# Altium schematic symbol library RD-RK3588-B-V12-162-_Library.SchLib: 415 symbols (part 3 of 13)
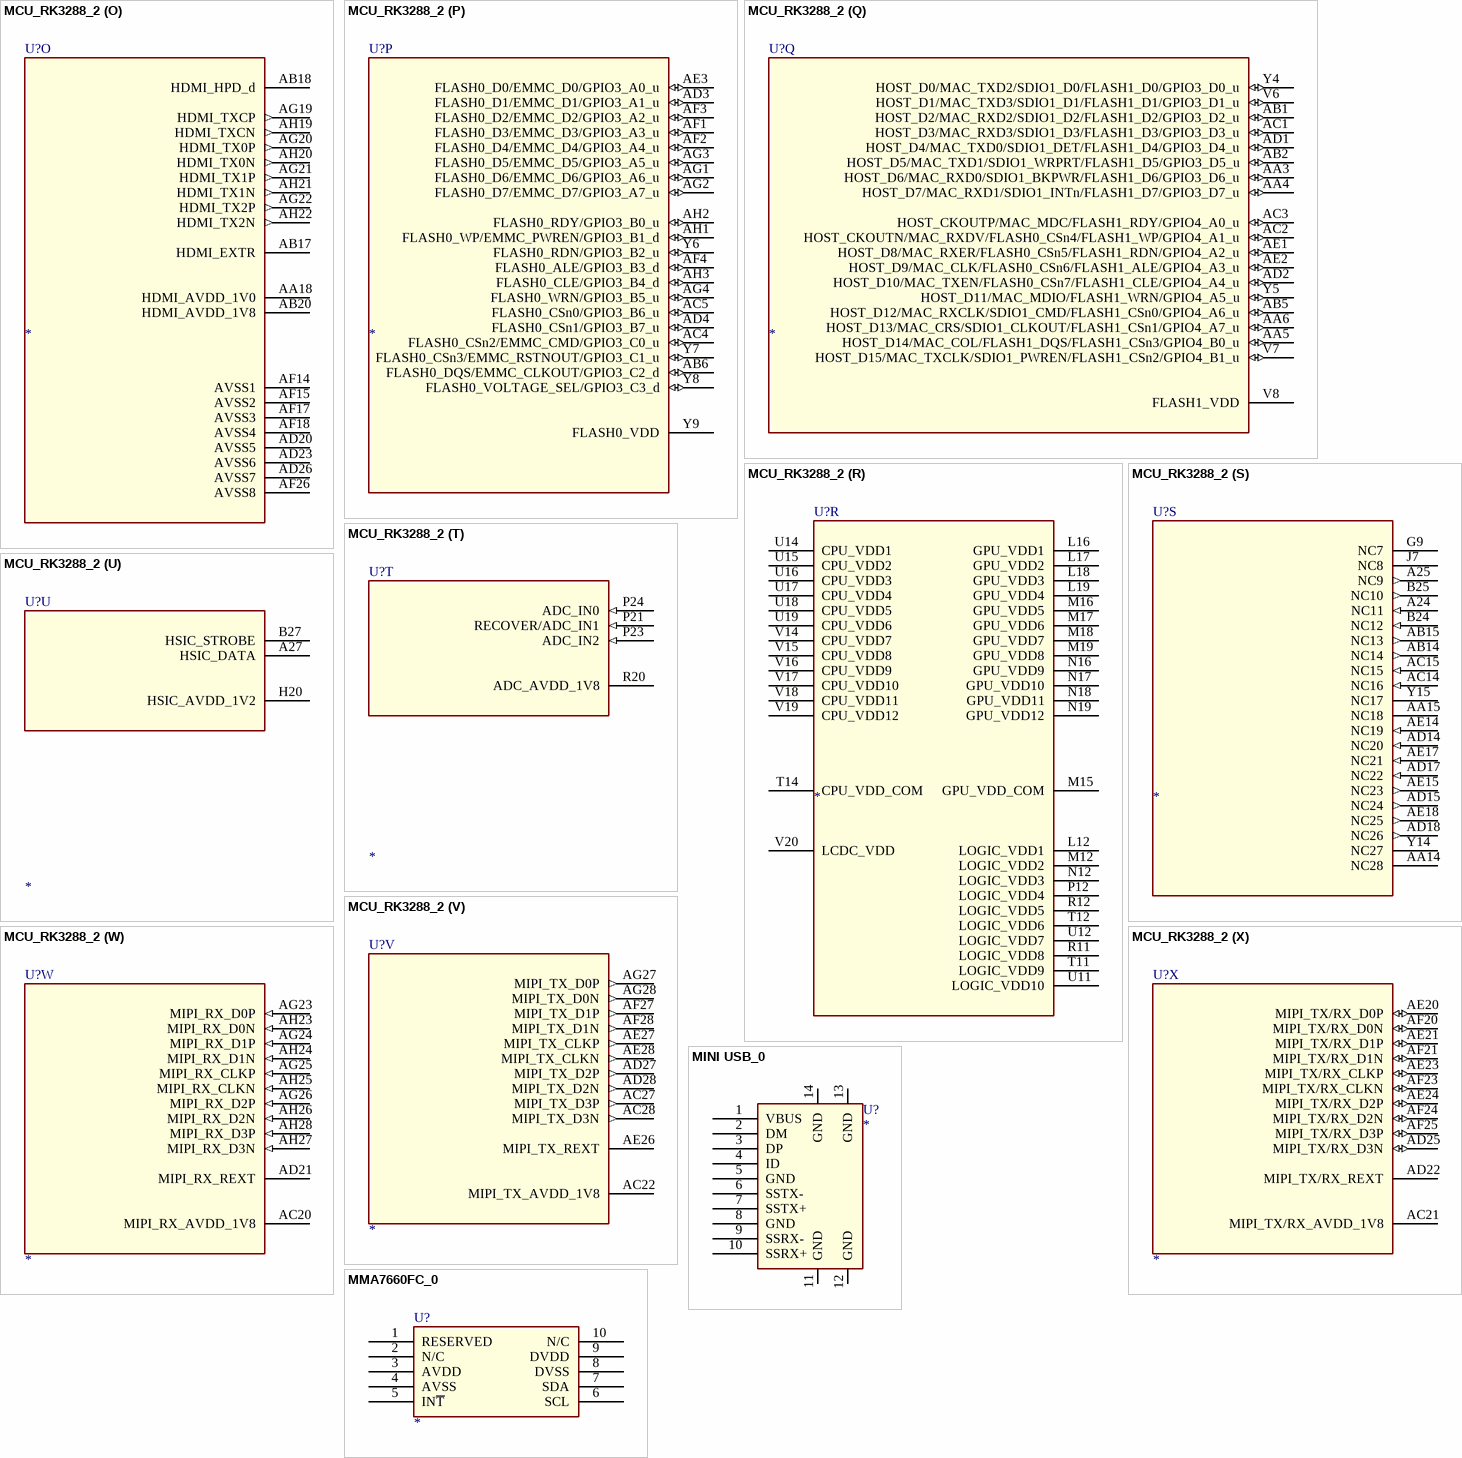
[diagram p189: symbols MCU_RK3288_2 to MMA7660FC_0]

## MCU_RK3288_2
designator U?
footprint BGA453-19X19
part A pins: AA20 LVDS_AVDD_1V0 (power), AA22 LCDC0_DEN/GPIO1_D2_d (io), AA23 LCDC0_HSYNC/GPIO1_D0_d (io), AA24 LCDC0_DCLK/GPIO1_D3_d (io), AA25 TRACE_CLK/LCDC0_D16/LVDS_D7P (io), AA26 TRACE_CTL/LCDC0_D17/LVDS_D7N (io), AA27 TRACE_D8/LCDC0_D8/LVDS_D4P (io), AA28 TRACE_D9/LCDC0_D9/LVDS_D4N (io), AB21 LVDS_AVDD_1V8 (power), AB23 LVDS_AVDD_3V3 (power), AB24 LCDC0_VSYNC/GPIO1_D1_d (io), AB27 LCDC0_D18/LVDS_D8P (io), AB28 LCDC0_D19/LVDS_D8N (io), AC25 LCDC0_D20/LVDS_D9P (io), AC26 LCDC0_D21/LVDS_D9N (io), T27 TRACE_D0/LCDC0_D0/LVDS_D0P (io), T28 TRACE_D1/LCDC0_D1/LVDS_D0N (io), U25 TRACE_D12/LCDC0_D12/LVDS_D5P (io), U26 TRACE_D13/LCDC0_D13/LVDS_D5N (io), U27 TRACE_D2/LCDC0_D2/LVDS_D1P (io), U28 TRACE_D3/LCDC0_D3/LVDS_D1N (io), V24 LVDS_EXTR, V25 TRACE_D14/LCDC0_D14/LVDS_D6P (io), V26 TRACE_D15/LCDC0_D15/LVDS_D6N (io), V27 TRACE_D10/LCDC0_D10/LVDS_CLK0P (io), V28 TRACE_D11/LCDC0_D11/LVDS_CLK0N (io), W27 TRACE_D4/LCDC0_D4/LVDS_D2P (io), W28 TRACE_D5/LCDC0_D5/LVDS_D2N (io), Y25 LCDC0_D22/LVDS_CLK1P (io), Y26 LCDC0_D23/LVDS_CLK1N (io), Y27 TRACE_D6/LCDC0_D6/LVDS_D3P (io), Y28 TRACE_D7/LCDC0_D7/LVDS_D3N (io)
part B pins: AB9 JTAG_TCK/SDMMC0_D3/GPIO6_C3_u (io), AC8 SDMMC0_CMD/GPIO6_C5_u (io), AC9 SDMMC0_VDD (power), AD8 JTAG_TDI/SDMMC0_D2/GPIO6_C2_u (io), AG6 JTAG_TDO/SDMMC0_CLKOUT/GPIO6_C4_d (io), AG7 JTAG_TMS/SDMMC0_D0/GPIO6_C0_u (io), AH5 SDMMC0_DET/GPIO6_C6_u (io), AH6 JTAG_TRSTN/SDMMC0_D1/GPIO6_C1_u (io)
part C pins: P22 I2C3_SCL/GPIO2_C0_u (io), R21 CIF_D11/GPIO2_B7_d (io), R22 HOST_WKREQ/TS_FAIL/CIF_CLKOUT/GPIO2_B3_d (io), R23 I2C3_SDA/GPIO2_C1_u (io), R24 CIF_D10/GPIO2_B6_d (io), R25 HOST_D6/TS_SYNC/CIF_VSYNC/GPIO2_B0_d (io), R26 CIF_D1/GPIO2_B5_d (io), R27 CIF_D0/GPIO2_B4_d (io), R28 HOST_D7/TS_VALID/CIF_HREF/GPIO2_B1_d (io), U20 DVPIO_VDD (power), U21 HOST_CKINN/TS_D5/CIF_D7/GPIO2_A5_d (io), U22 HOST_CKINP/TS_D4/CIF_D6/GPIO2_A4_d (io), U23 HOST_D4/TS_D6/CIF_D8/GPIO2_A6_d (io), V21 HOST_D3/TS_D3/CIF_D5/GPIO2_A3_d (io), V22 HOST_WKACK/GPS_CLK/TS_CLKOUT/CIF_CLKIN/GPIO2_B2_d (io), V23 HOST_D5/TS_D7/CIF_D9/GPIO2_A7_d (io), Y21 HOST_D1/TS_D1/CIF_D3/GPIO2_A1_d (io), Y22 HOST_D2/TS_D2/CIF_D4/GPIO2_A2_d (io), Y23 HOST_D0/TS_D0/CIF_D2/GPIO2_A0_d (io)
part D pins: J26 DDRIO_RETEN/PMUGPIO0_A2_u (io), J27 DDRIO_PWROFF/PMUGPIO0_A1_d (io), J28 GLOBAL_PWROFF/PMUGPIO0_A0_d (io), K27 EFUSE_PWREN/PMUGPIO0_A3_u (io), K28 PMUGPIO0_A4_u, L21 PMUGPIO0_A5_u, L22 PMUGPIO0_A6_u (io), L23 PMUGPIO0_A7_u (io), L24 PMUGPIO0_B0_u, L25 PMUGPIO0_B1_u, L26 OTP_OUT/PMUGPIO0_B2_d (io), L27 PMUGPIO0_B3_d (io), L28 CLK27M_IN/PMUGPIO0_B5_d (io), M20 PMU_VDD_1V0 (power), M21 I2C0_SCL/PMUGPIO0_C0_u (io), M22 PMUGPIO0_B6_d (io), M23 TEST_CLKO/CLK_27M_T1/PMUGPIO0_C1_d (io), M24 PMUGPIO0_C2_u (io), M25 I2C0_SDA/PMUGPIO0_B7_u (io), M26 TEST, M27 NPOR (in), M28 PMUGPIO0_B4_d (io), N27 OSC_XI (in), N28 OSC_XO (out), P19 EFUSE_VQPS (power), P20 PUMIO_VDD (power), P25 CLKIN_32K (in), P26 OSC_XVSS (power), P27 PLL_AVSS (power), P28 PLL_AVDD_1V0 (power)
part E pins: A22 HOST2_DM (io), A23 HOST1_DM (io), A26 OTG_DM (io), B21 USB_AVSS4 (power), B22 HOST2_DP (io), B23 HOST1_DP (io), B26 OTG_DP (io), C21 HOST2_EXTR, C23 HOST1_EXTR, C24 USB_AVSS2 (power), C25 OTG_ID, C26 USB_AVSS3 (power), D21 OTG_EXTR, D23 OTG_VBUS, E21 USB_AVDD_1V8 (power), F20 USB_AVDD_3V3 (power), G18 USB_AVDD_1V0 (power), H18 USB_AVSS1 (power)
part F pins: D28 GPIO7_A2_d (io), E26 GPIO7_A4_u (io), E27 GPS_MAG/HSADC_D0_T1/UART3_RX/GPIO7_A7_u, E28 eDP_HOTPLUG/GPIO7_B3_d (io), F25 GPIO7_A3_d (io), F26 GPIO7_A6_u (io), F27 UART3_RTSn/GPIO7_B2_u (io), F28 ISP_PRELIGHTTRIG/SPI1_RXD/GPIO7_B6_d (io), G23 PWM1/GPIO7_A1_d (io), G24 GPIO7_A5_d (io), G27 ISP_SHUTTERTRIG/SPI1_TXD/GPIO7_B7_d (io), G28 ISP_FLASHTRIGIN/EDPHDMI_CEC_T1/GPIO7_C0_u (io), H22 PWM0/GPIO7_A0_d (io), H23 GPS_RFCLK/GPS_CLK_T1/UART3_CTSn/GPIO7_B1_u (io), H24 ISP_FLASHTRIGOUT/SPI1_CSN0/GPIO7_B5_u (io), H25 I2C4_SDA/GPIO7_C1_u (io), H26 I2C5_SDA/EDPHDMI_I2C_SDA/GPIO7_C3_u (io), H27 GPIO7_C5_d (io), H28 UART2_TX/IR_TX/PWM3/EDPHDMI_CEC/GPIO7_C7_u (io), J21 GPS_SIG/HSADC_D1_T1/UART3_TX/GPIO7_B0_d (io), J22 ISP_SHUTTEREN/SPI1_CLK/GPIO7_B4_d (io), J23 I2C4_SCL/GPIO7_C2_u (io), J24 I2C5_SCL/EDPHDMI_I2C_SCL/GPIO7_C4_u (io), J25 UART2_RX/IR_RX/PWM2/GPIO7_C6_u, L20 APIO1_VDD (power)
part G pins: A28 I2C1_SDA/SC_RST/GPIO8_A4_u (io), B28 SPI2_CSn1/SC_IO/GPIO8_A3_u (io), C27 PS2_DATA/GPIO8_A1_u (io), C28 SPI2_TXD/SC_CLK_T1/GPIO8_B1_d (io), D24 PS2_CLK/GPIO8_A0_u (io), D26 SPI2_CLK/SC_IO_T1/GPIO8_A6_d (io), D27 SPI2_CSn0/SC_DET_T1/GPIO8_A7_u (io), E22 BS_JTAG_TRSTn (out), E23 BS_JTAG_TCK (out), E25 I2C1_SCL/SC_CLK/GPIO8_A5_u (io), F21 BS_JTAG_TDI (in), F22 BS_JTAG_TDO (out), F24 SPI2_RXD/SC_RST_T1/GPIO8_B0_d (io), G20 BS_JTAG_TMS (out), G21 SC_DET/GPIO8_A2_u (io), J20 APIO2_VDD (power)
part H pins: AA11 APIO3_VDD (power), AB11 UART0_RTSn/GPIO4_C3_u (io), AB12 UART0_CTSn/GPIO4_C2_u (io), AC11 SDIO0_PWR/GPIO4_D4_d (io), AD9 GPIO4_D7_u (io), AE8 SDIO0_INTn/GPIO4_D6_u (io), AE9 SDIO0_WP/GPIO4_D3_d (io), AF8 SDIO0_BKPWR/GPIO4_D5_d (io), AF9 SDIO0_DET/GPIO4_D2_u (io), AG8 SDIO0_CLKOUT/GPIO4_D1_d (io), AG9 SDIO0_D2/GPIO4_C6_u (io), AG10 UART0_TXD/GPIO4_C1_d (io), AH7 SDIO0_D3/GPIO4_C7_u (io), AH8 SDIO0_CMD/GPIO4_D0_u (io), AH9 SDIO0_D0/GPIO4_C4_u (io), AH10 SDIO0_D1/GPIO4_C5_u (io), AH11 UART0_RXD/GPIO4_C0_u (io)
part I pins: AC12 I2S_CLK/GPIO6_B0_d (io), AD11 I2S_SCLK/GPIO6_A0_d (io), AD12 I2C2_SCL/GPIO6_B2_u (io), AE11 I2S_SDI/GPIO6_A3_d (io), AE12 SPDIF_TX/GPIO6_B3_d (io), AF11 I2S_LRCK_TX/GPIO6_A2_d (io), AF12 I2C2_SDA/GPIO6_B1_u (io), AG11 I2S_LRCK_RX/GPIO6_A1_d (io), AG12 I2S_SDO0/GPIO6_A4_d (io), AG13 I2S_SDO2/GPIO6_A6_d (io), AH12 I2S_SDO3/GPIO6_A7_d (io), AH13 I2S_SDO1/GPIO6_A5_d (io), Y12 APIO4_VDD (power)
part J pins: AA7 UART1_TX/TS0_D1/GPIO5_B1_d (io), AA9 TS0_VALID/GPIO5_C1_d (io), AB8 TS0_ERR/GPIO5_C3_d (io), AC7 SPI0_CSn0/UART4_RTSn/TS0_D5/GPIO5_B5_u (io), AD6 UART1_RTSn/TS0_D3/GPIO5_B3_u (io), AD7 SPI0_CLK/UART4_CTSn/TS0_D4/GPIO5_B4_u (io), AE5 SPI0_TXD/UART4_TX/TS0_D6/GPIO5_B6_d, AE6 TS0_CLK/GPIO5_C2_d (io), AF5 UART1_RX/TS0_D0/GPIO5_B0_u, AF6 SPI0_RXD/UART4_RX/TS0_D7/GPIO5_B7_u, AG5 SPI0_CSn1/TS0_SYNC/GPIO5_C0_u (io), AH4 UART1_CTSn/TS0_D2/GPIO5_B2_u (io), Y11 APIO5_VDD (power)
part K pins: A1 DDR0_DQ25 (io), A2 DDR0_DQ24 (io), A3 DDR0_DQ10 (io), A4 DDR0_DQS3n (out), A5 DDR0_DQ9 (io), A6 DDR0_DQ13 (io), A7 DDR0_DQS1n (out), A8 DDR0_CASn (out), A9 DDR0_BA1 (out), A10 DDR0_A2 (out), A11 DDR0_CLKn (out), A12 DDR0_A7 (out), A13 DDR0_A10 (out), A14 DDR0_A9 (out), A15 DDR0_DM2 (out), A16 DDR0_DQ17 (io), A17 DDR0_DQS2n (out), A18 DDR0_DQ23 (io), A19 DDR0_DQ4 (io), A20 DDR0_DQS0 (out), B3 DDR0_DM3 (out), B4 DDR0_DQS3 (out), B5 DDR0_DQ8 (io), B6 DDR0_DQ14 (io), B7 DDR0_DQS1 (out), B8 DDR0_CSn0 (out), B9 DDR0_WEn (out), B10 DDR0_A0 (out), B11 DDR0_CLK (out), B12 DDR0_A5 (out), B13 DDR0_A8 (out), B14 DDR0_A14 (out), B15 DDR0_DQ16 (io), B16 DDR0_DQ19 (io), B17 DDR0_DQS2 (out), B18 DDR0_DQ21 (io), B19 DDR0_DQ0 (io), B20 DDR0_DQS0n (out), C4 DDR0_DQ30 (io), C5 DDR0_DQ28 (io), C6 DDR0_DQ11 (io), C8 DDR0_CKE1 (out), C9 DDR0_CKE0 (out), C11 DDR0_A1 (out), C12 DDR0_A6 (out), C14 DDR0_A13 (out), C15 DDR0_A15 (out), C17 DDR0_DQ22 (io), C18 DDR0_DQ1 (io), C20 DDR0_DQ6 (io), D5 DDR0_DQ26 (io), D8 DDR0_BA0 (out), D11 DDR0_RASn (out), D14 DDR0_A11 (out), D17 DDR0_DQ20 (io), D20 DDR0_DQ7 (io), E6 DDR0_DQ27 (io), E7 DDR0_DQ31 (io), E8 DDR0_DQ12 (io), E9 DDR0_RESET (out), E11 DDR0_BA2 (out), E12 DDR0_A3 (out), E14 DDR0_ODT0 (out), E15 DDR0_ODT1 (out), E17 DDR0_DM0 (out), E18 DDR0_DQ5 (io), F7 DDR0_DQ29 (io), F8 DDR0_DQ15 (io), F9 DDR0_DM1 (out), F11 DDR0_CSn1 (out), F12 DDR0_A4 (out), F14 DDR0_A12 (out), F15 DDR0_DQ18 (io), F17 DDR0_DQ2 (io), F18 DDR0_DQ3 (io), G8 DDR0_RETLE, G11 NC3, G12 DDR0_ATO, G14 NC1, G15 NC2, G17 DDR0_PZQ, H9 DDR0_VDD1 (power), H11 DDR0_VREFAO (power), H12 DDR0_VREF (power), H14 DDR0_VDDAO (power), H15 DDR0_DTO1, H17 DDR0_DTO0, J11 DDR0_VDD2 (power), J12 DDR0_VDD3 (power), J14 DDR0_VDD4 (power), J15 DDR0_VDD5 (power)
part L pins: AA1 DDR1_DQS0n (out), AA2 DDR1_DQS0 (out), B1 DDR1_DQ24 (io), B2 DDR1_DQ25 (io), C1 DDR1_DQ10 (io), C2 DDR1_DQ30 (io), D1 DDR1_DQS3n (out), D2 DDR1_DQS3 (out), D3 DDR1_DM3 (out), E1 DDR1_DQ9 (io), E2 DDR1_DQ8 (io), E3 DDR1_DQ28 (io), E4 DDR1_DQ26 (io), F1 DDR1_CKE0 (out), F2 DDR1_RESET (out), F3 DDR1_DQ11 (io), F5 DDR1_DQ29 (io), G1 DDR1_DQS1n (out), G2 DDR1_DQS1 (out), G5 DDR1_DM1 (out), G6 DDR1_DQ27 (io), H1 DDR1_CASn (out), H2 DDR1_CSn0 (out), H3 DDR1_CKE1 (out), H4 DDR1_DQ13 (io), H5 DDR1_DQ12 (io), H6 DDR1_DQ31 (io), H7 DDR1_RETLE, J1 DDR1_BA1 (out), J2 DDR1_WEn (out), J3 DDR1_CSn1 (out), J5 DDR1_DQ14 (io), J6 DDR1_DQ15 (io), J8 DDR1_VDD1 (power), K1 DDR1_A2 (out), K2 DDR1_A1 (out), L1 DDR1_CLKn (out), L2 DDR1_CLK (out), L3 DDR1_A0 (out), L4 DDR1_BA0 (out), L5 DDR1_BA2 (out), L6 DDR1_RASn (out), L7 NC6, L8 DDR1_VREFAO (power), L9 DDR1_VDD2 (power), M1 DDR1_A6 (out), M2 DDR1_A5 (out), M3 DDR1_A7 (out), M5 DDR1_A3 (out), M6 DDR1_A4 (out), M7 DDR1_ATO, M8 DDR1_VREF (power), M9 DDR1_VDD3 (power), N1 DDR1_A8 (out), N2 DDR1_A10 (out), P1 DDR1_A9 (out), P2 DDR1_A14 (out), P3 DDR1_A13 (out), P4 DDR1_A11 (out), P5 DDR1_ODT0 (out), P6 DDR1_A12 (out), P7 NC4, P8 DDR1_VDDAO (power), P9 DDR1_VDD4 (power), R1 DDR1_A15 (out), R2 DDR1_ODT1 (out), R3 DDR1_DM2 (out), R5 DDR1_DQ19 (io), R6 DDR1_DQ17 (io), R7 NC5, R8 DDR1_DTO1, R9 DDR1_VDD5 (power), T1 DDR1_DQ18 (io), T2 DDR1_DQ16 (io), U1 DDR1_DQS2n (out), U2 DDR1_DQS2 (out), U3 DDR1_DQ22 (io), U4 DDR1_DQ20 (io), U5 DDR1_DM0 (out), U6 DDR1_DQ3 (io), U7 DDR1_PZQ, U8 DDR1_DTO0, V1 DDR1_DQ21 (io), V2 DDR1_DQ23 (io), V3 DDR1_DQ1 (io), V5 DDR1_DQ6 (io), W1 DDR1_DQ4 (io), W2 DDR1_DQ0 (io), Y1 DDR1_DQ2 (io), Y2 DDR1_DQ5 (io), Y3 DDR1_DQ7 (io)
part M pins: A21 VSS9 (power), AC24 VSS11 (power), C3 VSS1 (power), D6 VSS2 (power), D9 VSS3 (power), D12 VSS4 (power), D15 VSS5 (power), D18 VSS6 (power), E20 VSS7 (power), F4 VSS12 (power), J4 VSS13 (power), J9 VSS14 (power), J17 VSS16 (power), J18 VSS28 (power), K10 VSS18 (power), K11 VSS19 (power), K12 VSS20 (power), K13 VSS21 (power), K14 VSS22 (power), K15 VSS23 (power), K16 VSS24 (power), K17 VSS25 (power), K18 VSS26 (power), K19 VSS27 (power), L10 VSS29 (power), L11 VSS30 (power), L13 VSS31 (power), L14 VSS32 (power), L15 VSS33 (power), M4 VSS34 (power), M10 VSS35 (power), M11 VSS36 (power), M13 VSS37 (power), M14 VSS38 (power), N10 VSS40 (power), N11 VSS41 (power), N13 VSS42 (power), N14 VSS43 (power), N15 VSS44 (power), P10 VSS45 (power), P11 VSS46 (power), P13 VSS47 (power), P14 VSS48 (power), P15 VSS49 (power), P16 VSS50 (power), P17 VSS51 (power), P18 VSS52 (power), R4 VSS53 (power), R10 VSS54 (power), R13 VSS55 (power), R14 VSS61 (power), R15 VSS71 (power), R16 VSS56 (power), R17 VSS57 (power), R18 VSS58 (power), R19 VSS59 (power), T10 VSS60 (power), T13 VSS62 (power), T15 VSS64 (power), T16 VSS65 (power), T17 VSS66 (power), T18 VSS67 (power), T19 VSS68 (power), U9 VSS15 (power), U10 VSS70 (power), U13 VSS72 (power), U24 VSS8 (power), V4 VSS73 (power), V9 VSS69 (power), V10 VSS74 (power), V11 VSS75 (power), V12 VSS76 (power), V13 VSS77 (power), W10 VSS17 (power), W11 VSS78 (power), W12 VSS79 (power), W13 VSS80 (power), W14 VSS81 (power), W15 VSS82 (power), W16 VSS83 (power), W17 VSS84 (power), W18 VSS85 (power), W19 VSS86 (power), Y18 VSS39 (power), Y20 VSS63 (power), Y24 VSS10 (power)
part N pins: AA12 eDP_TP_OUT, AA17 eDP_AVDD_1V8 (power), AC17 eDP_CLK24M_IN, AC18 eDP_EXTR, AG14 eDP_TX0P (out), AG15 eDP_TX1P (out), AG16 eDP_TX2P (out), AG17 eDP_TX3P (out), AG18 eDP_AXUP (out), AH14 eDP_TX0N (out), AH15 eDP_TX1N (out), AH16 eDP_TX2N (out), AH17 eDP_TX3N (out), AH18 eDP_AXUN (out), Y17 eDP_AVDD_1V0 (power)
part O pins: AA18 HDMI_AVDD_1V0 (power), AB17 HDMI_EXTR, AB18 HDMI_HPD_d, AB20 HDMI_AVDD_1V8 (power), AD20 AVSS5 (power), AD23 AVSS6 (power), AD26 AVSS7 (power), AF14 AVSS1 (power), AF15 AVSS2 (power), AF17 AVSS3 (power), AF18 AVSS4 (power), AF26 AVSS8 (power), AG19 HDMI_TXCP (out), AG20 HDMI_TX0P (out), AG21 HDMI_TX1P (out), AG22 HDMI_TX2P (out), AH19 HDMI_TXCN (out), AH20 HDMI_TX0N (out), AH21 HDMI_TX1N (out), AH22 HDMI_TX2N (out)
part P pins: AB6 FLASH0_DQS/EMMC_CLKOUT/GPIO3_C2_d (io), AC4 FLASH0_CSn2/EMMC_CMD/GPIO3_C0_u (io), AC5 FLASH0_CSn0/GPIO3_B6_u (io), AD3 FLASH0_D1/EMMC_D1/GPIO3_A1_u (io), AD4 FLASH0_CSn1/GPIO3_B7_u (io), AE3 FLASH0_D0/EMMC_D0/GPIO3_A0_u (io), AF1 FLASH0_D3/EMMC_D3/GPIO3_A3_u (io), AF2 FLASH0_D4/EMMC_D4/GPIO3_A4_u (io), AF3 FLASH0_D2/EMMC_D2/GPIO3_A2_u (io), AF4 FLASH0_ALE/GPIO3_B3_d (io), AG1 FLASH0_D6/EMMC_D6/GPIO3_A6_u (io), AG2 FLASH0_D7/EMMC_D7/GPIO3_A7_u (io), AG3 FLASH0_D5/EMMC_D5/GPIO3_A5_u (io), AG4 FLASH0_WRN/GPIO3_B5_u (io), AH1 FLASH0_WP/EMMC_PWREN/GPIO3_B1_d (io), AH2 FLASH0_RDY/GPIO3_B0_u (io), AH3 FLASH0_CLE/GPIO3_B4_d (io), Y6 FLASH0_RDN/GPIO3_B2_u (io), Y7 FLASH0_CSn3/EMMC_RSTNOUT/GPIO3_C1_u (io), Y8 FLASH0_VOLTAGE_SEL/GPIO3_C3_d (io), Y9 FLASH0_VDD (power)
part Q pins: AA3 HOST_D6/MAC_RXD0/SDIO1_BKPWR/FLASH1_D6/GPIO3_D6_u (io), AA4 HOST_D7/MAC_RXD1/SDIO1_INTn/FLASH1_D7/GPIO3_D7_u (io), AA5 HOST_D14/MAC_COL/FLASH1_DQS/FLASH1_CSn3/GPIO4_B0_u (io), AA6 HOST_D13/MAC_CRS/SDIO1_CLKOUT/FLASH1_CSn1/GPIO4_A7_u (io), AB1 HOST_D2/MAC_RXD2/SDIO1_D2/FLASH1_D2/GPIO3_D2_u (io), AB2 HOST_D5/MAC_TXD1/SDIO1_WRPRT/FLASH1_D5/GPIO3_D5_u (io), AB5 HOST_D12/MAC_RXCLK/SDIO1_CMD/FLASH1_CSn0/GPIO4_A6_u (io), AC1 HOST_D3/MAC_RXD3/SDIO1_D3/FLASH1_D3/GPIO3_D3_u (io), AC2 HOST_CKOUTN/MAC_RXDV/FLASH0_CSn4/FLASH1_WP/GPIO4_A1_u (io), AC3 HOST_CKOUTP/MAC_MDC/FLASH1_RDY/GPIO4_A0_u (io), AD1 HOST_D4/MAC_TXD0/SDIO1_DET/FLASH1_D4/GPIO3_D4_u (io), AD2 HOST_D10/MAC_TXEN/FLASH0_CSn7/FLASH1_CLE/GPIO4_A4_u (io), AE1 HOST_D8/MAC_RXER/FLASH0_CSn5/FLASH1_RDN/GPIO4_A2_u (io), AE2 HOST_D9/MAC_CLK/FLASH0_CSn6/FLASH1_ALE/GPIO4_A3_u (io), V6 HOST_D1/MAC_TXD3/SDIO1_D1/FLASH1_D1/GPIO3_D1_u (io), V7 HOST_D15/MAC_TXCLK/SDIO1_PWREN/FLASH1_CSn2/GPIO4_B1_u (io), V8 FLASH1_VDD (power), Y4 HOST_D0/MAC_TXD2/SDIO1_D0/FLASH1_D0/GPIO3_D0_u (io), Y5 HOST_D11/MAC_MDIO/FLASH1_WRN/GPIO4_A5_u (io)
part R pins: L12 LOGIC_VDD1 (power), L16 GPU_VDD1 (power), L17 GPU_VDD2 (power), L18 GPU_VDD3 (power), L19 GPU_VDD4 (power), M12 LOGIC_VDD2 (power), M15 GPU_VDD_COM, M16 GPU_VDD5 (power), M17 GPU_VDD6 (power), M18 GPU_VDD7 (power), M19 GPU_VDD8 (power), N12 LOGIC_VDD3 (power), N16 GPU_VDD9 (power), N17 GPU_VDD10 (power), N18 GPU_VDD11 (power), N19 GPU_VDD12 (power), P12 LOGIC_VDD4 (power), R11 LOGIC_VDD8 (power), R12 LOGIC_VDD5 (power), T11 LOGIC_VDD9 (power), T12 LOGIC_VDD6 (power), T14 CPU_VDD_COM, U11 LOGIC_VDD10 (power), U12 LOGIC_VDD7 (power), U14 CPU_VDD1 (power), U15 CPU_VDD2 (power), U16 CPU_VDD3 (power), U17 CPU_VDD4 (power), U18 CPU_VDD5 (power), U19 CPU_VDD6 (power), V14 CPU_VDD7 (power), V15 CPU_VDD8 (power), V16 CPU_VDD9 (power), V17 CPU_VDD10 (power), V18 CPU_VDD11 (power), V19 CPU_VDD12 (power), V20 LCDC_VDD (power)
part S pins: A24 NC11 (in), A25 NC9 (out), AA14 NC28 (power), AA15 NC18 (power), AB14 NC14 (out), AB15 NC13 (out), AC14 NC16 (in), AC15 NC15 (in), AD14 NC20 (in), AD15 NC24 (out), AD17 NC22 (in), AD18 NC26 (out), AE14 NC19 (in), AE15 NC23 (out), AE17 NC21 (in), AE18 NC25 (out), B24 NC12 (in), B25 NC10 (out), G9 NC7, J7 NC8, Y14 NC27 (power), Y15 NC17 (power)
part T pins: P21 RECOVER/ADC_IN1 (in), P23 ADC_IN2 (in), P24 ADC_IN0 (in), R20 ADC_AVDD_1V8 (power)
part U pins: A27 HSIC_DATA, B27 HSIC_STROBE, H20 HSIC_AVDD_1V2 (power)
part V pins: AC22 MIPI_TX_AVDD_1V8 (power), AC27 MIPI_TX_D3P (out), AC28 MIPI_TX_D3N (out), AD27 MIPI_TX_D2P (out), AD28 MIPI_TX_D2N (out), AE26 MIPI_TX_REXT, AE27 MIPI_TX_CLKP (out), AE28 MIPI_TX_CLKN (out), AF27 MIPI_TX_D1P (out), AF28 MIPI_TX_D1N (out), AG27 MIPI_TX_D0P (out), AG28 MIPI_TX_D0N (out)
part W pins: AC20 MIPI_RX_AVDD_1V8 (power), AD21 MIPI_RX_REXT, AG23 MIPI_RX_D0P (in), AG24 MIPI_RX_D1P (in), AG25 MIPI_RX_CLKP (in), AG26 MIPI_RX_D2P (in), AH23 MIPI_RX_D0N (in), AH24 MIPI_RX_D1N (in), AH25 MIPI_RX_CLKN (in), AH26 MIPI_RX_D2N (in), AH27 MIPI_RX_D3N (in), AH28 MIPI_RX_D3P (in)
part X pins: AC21 MIPI_TX/RX_AVDD_1V8 (power), AD22 MIPI_TX/RX_REXT, AD25 MIPI_TX/RX_D3N (io), AE20 MIPI_TX/RX_D0P (io), AE21 MIPI_TX/RX_D1P (io), AE23 MIPI_TX/RX_CLKP (io), AE24 MIPI_TX/RX_D2P (io), AF20 MIPI_TX/RX_D0N (io), AF21 MIPI_TX/RX_D1N (io), AF23 MIPI_TX/RX_CLKN (io), AF24 MIPI_TX/RX_D2N (io), AF25 MIPI_TX/RX_D3P (io)

## MINI USB_0
designator U?
pins: 1 VBUS, 2 DM, 3 DP, 4 ID, 5 GND, 6 SSTX-, 7 SSTX+, 8 GND (power), 9 SSRX-, 10 SSRX+, 11 GND, 12 GND, 13 GND, 14 GND

## MMA7660FC_0
designator U?
pins: 1 RESERVED, 2 N/C, 3 AVDD, 4 AVSS, 5 IN~{T}, 6 SCL, 7 SDA, 8 DVSS, 9 DVDD, 10 N/C

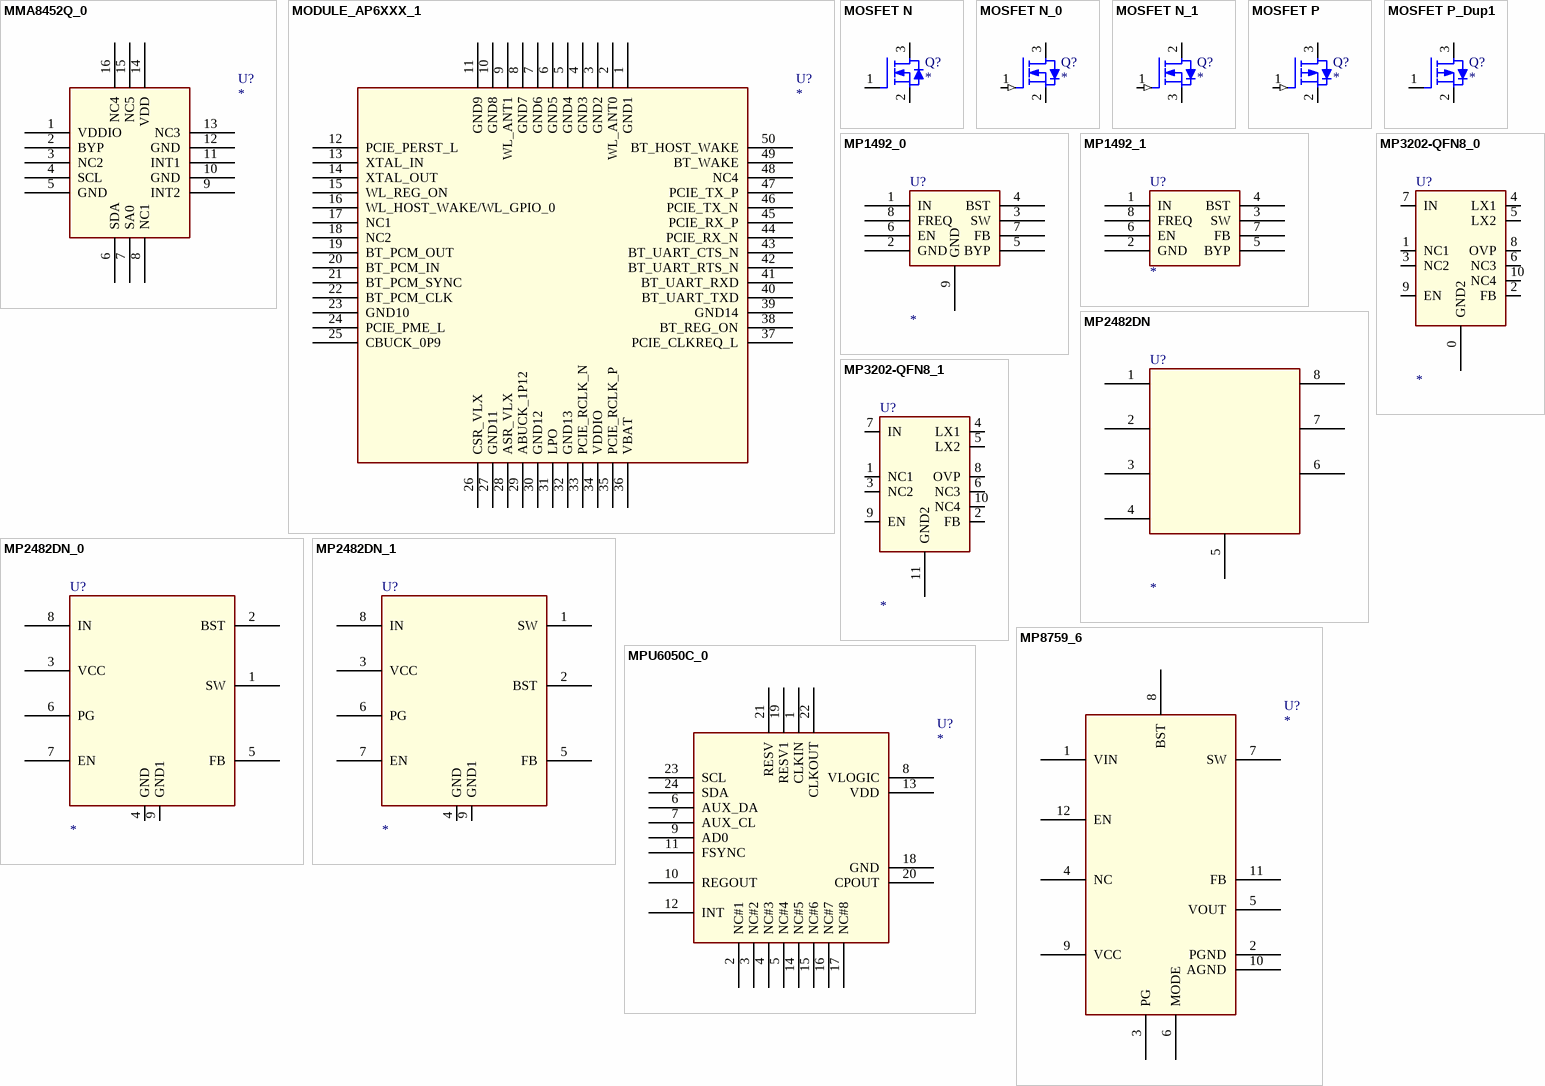
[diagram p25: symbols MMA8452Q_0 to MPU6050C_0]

## MMA8452Q_0
designator U?
footprint QFN16_COL
pins: 1 VDDIO, 2 BYP, 3 NC2, 4 SCL, 5 GND (power), 6 SDA, 7 SA0, 8 NC1, 9 INT2, 10 GND (power), 11 INT1, 12 GND (power), 13 NC3, 14 VDD, 15 NC5, 16 NC4

## MODULE_AP6XXX_1
designator U?
pins: 1 GND1, 2 WL_ANT0, 3 GND2, 4 GND3, 5 GND4, 6 GND5, 7 GND6, 8 GND7, 9 WL_ANT1, 10 GND8, 11 GND9, 12 PCIE_PERST_L, 13 XTAL_IN, 14 XTAL_OUT, 15 WL_REG_ON, 16 WL_HOST_WAKE/WL_GPIO_0, 17 NC1, 18 NC2, 19 BT_PCM_OUT, 20 BT_PCM_IN, 21 BT_PCM_SYNC, 22 BT_PCM_CLK, 23 GND10, 24 PCIE_PME_L, 25 CBUCK_0P9, 26 CSR_VLX, 27 GND11, 28 ASR_VLX, 29 ABUCK_1P12, 30 GND12, 31 LPO, 32 GND13, 33 PCIE_RCLK_N, 34 VDDIO, 35 PCIE_RCLK_P, 36 VBAT, 37 PCIE_CLKREQ_L, 38 BT_REG_ON, 39 GND14, 40 BT_UART_TXD, 41 BT_UART_RXD, 42 BT_UART_RTS_N, 43 BT_UART_CTS_N, 44 PCIE_RX_N, 45 PCIE_RX_P, 46 PCIE_TX_N, 47 PCIE_TX_P, 48 NC4, 49 BT_WAKE, 50 BT_HOST_WAKE

## MOSFET N
designator Q?
footprint SOT23
pins: 1 GATE, 2 SOURCE, 3 DRAIN

## MOSFET N_0
designator Q?
pins: 1 GATE (in), 2 SOURCE, 3 DRAIN

## MOSFET N_1
designator Q?
pins: 1 GATE (in), 2 DRAIN, 3 SOURCE

## MOSFET P
designator Q?
footprint SOT23
pins: 1 GATE (in), 2 SOURCE, 3 DRAIN

## MOSFET P_Dup1
designator Q?
footprint SOT23
pins: 1 GATE, 2 SOURCE, 3 DRAIN

## MP1492_0
designator U?
footprint SOP8A
pins: 1 IN, 2 GND, 3 SW, 4 BST, 5 BYP, 6 EN, 7 FB, 8 FREQ, 9 GND

## MP1492_1
designator U?
footprint SOP8A
pins: 1 IN, 2 GND, 3 SW, 4 BST, 5 BYP, 6 EN, 7 FB, 8 FREQ

## MP2482DN
designator U?
pins: 1, 2, 3, 4, 5, 6, 7, 8

## MP2482DN_0
designator U?
pins: 1 SW, 2 BST, 3 VCC, 4 GND, 5 FB, 6 PG, 7 EN, 8 IN, 9 GND1

## MP2482DN_1
designator U?
pins: 1 SW, 2 BST, 3 VCC, 4 GND, 5 FB, 6 PG, 7 EN, 8 IN, 9 GND1

## MP3202-QFN8_0
designator U?
footprint QFN8-2X2
pins: 0 GND2, 1 NC1, 2 FB, 3 NC2, 4 LX1, 5 LX2, 6 NC3, 7 IN, 8 OVP, 9 EN, 10 NC4

## MP3202-QFN8_1
designator U?
footprint QFN8-2X2
pins: 1 NC1, 2 FB, 3 NC2, 4 LX1, 5 LX2, 6 NC3, 7 IN, 8 OVP, 9 EN, 10 NC4, 11 GND2

## MP8759_6
designator U?
footprint QFN12_2R00X3R00X1R00
pins: 1 VIN, 2 PGND, 3 PG, 4 NC, 5 VOUT, 6 MODE, 7 SW, 8 BST, 9 VCC, 10 AGND, 11 FB, 12 EN

## MPU6050C_0
designator U?
pins: 1 CLKIN, 2 NC#1, 3 NC#2, 4 NC#3, 5 NC#4, 6 AUX_DA, 7 AUX_CL, 8 VLOGIC, 9 AD0, 10 REGOUT, 11 FSYNC, 12 INT, 13 VDD, 14 NC#5, 15 NC#6, 16 NC#7, 17 NC#8, 18 GND, 19 RESV1, 20 CPOUT, 21 RESV, 22 CLKOUT, 23 SCL, 24 SDA

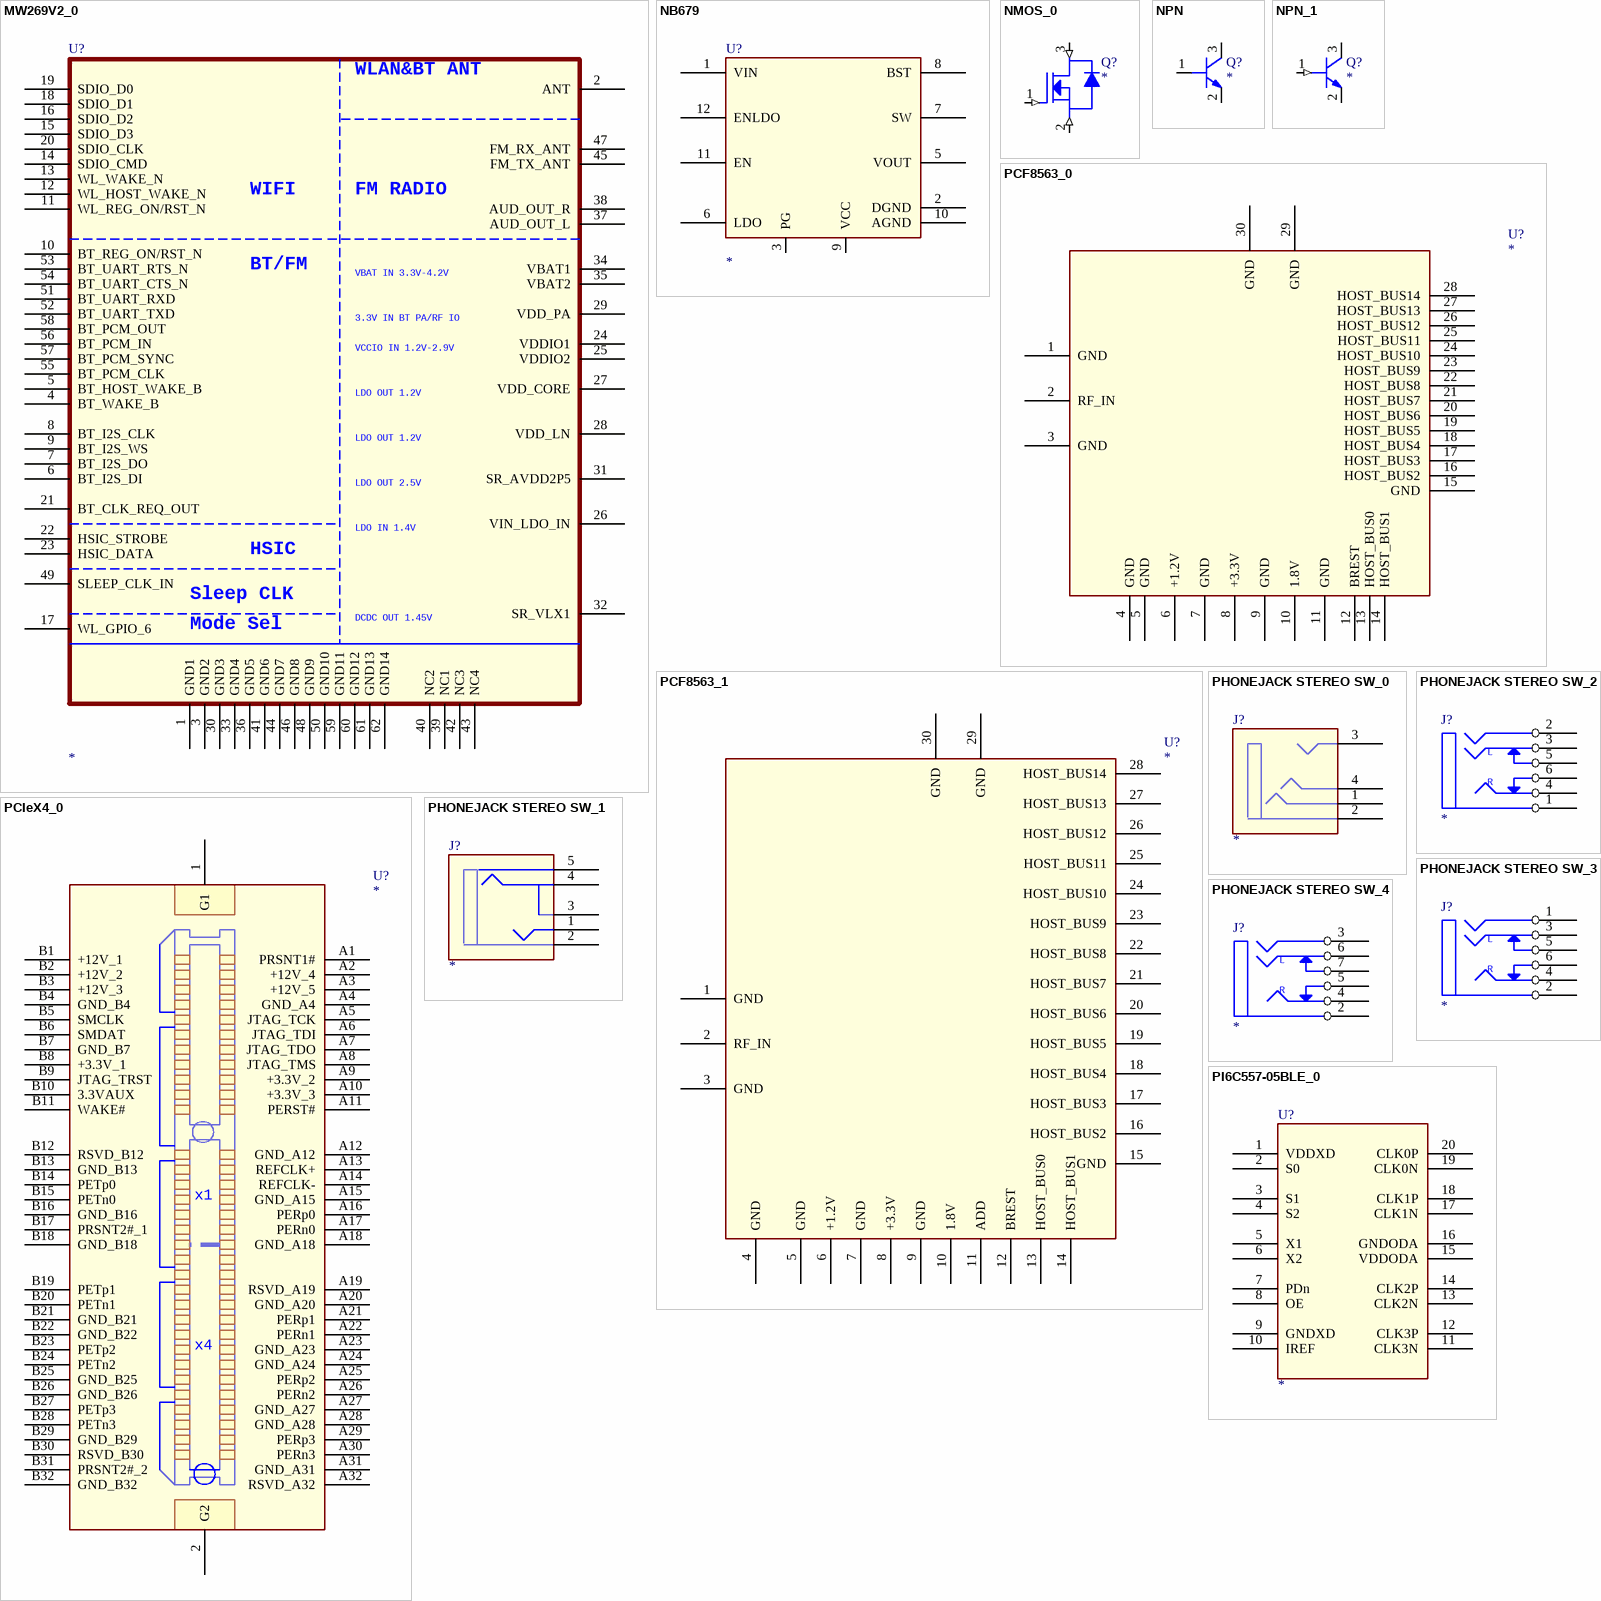
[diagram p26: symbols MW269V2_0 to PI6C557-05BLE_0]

## MW269V2_0
designator U?
footprint MW269V2
pins: 1 GND1, 2 ANT, 3 GND2, 4 BT_WAKE_B, 5 BT_HOST_WAKE_B, 6 BT_I2S_DI, 7 BT_I2S_DO, 8 BT_I2S_CLK, 9 BT_I2S_WS, 10 BT_REG_ON/RST_N, 11 WL_REG_ON/RST_N, 12 WL_HOST_WAKE_N, 13 WL_WAKE_N, 14 SDIO_CMD, 15 SDIO_D3, 16 SDIO_D2, 17 WL_GPIO_6, 18 SDIO_D1, 19 SDIO_D0, 20 SDIO_CLK, 21 BT_CLK_REQ_OUT, 22 HSIC_STROBE, 23 HSIC_DATA, 24 VDDIO1, 25 VDDIO2, 26 VIN_LDO_IN, 27 VDD_CORE, 28 VDD_LN, 29 VDD_PA, 30 GND3, 31 SR_AVDD2P5, 32 SR_VLX1, 33 GND4, 34 VBAT1, 35 VBAT2, 36 GND5, 37 AUD_OUT_L, 38 AUD_OUT_R, 39 NC1, 40 NC2, 41 GND6, 42 NC3, 43 NC4, 44 GND7, 45 FM_TX_ANT, 46 GND8, 47 FM_RX_ANT, 48 GND9, 49 SLEEP_CLK_IN, 50 GND10, 51 BT_UART_RXD, 52 BT_UART_TXD, 53 BT_UART_RTS_N, 54 BT_UART_CTS_N, 55 BT_PCM_CLK, 56 BT_PCM_IN, 57 BT_PCM_SYNC, 58 BT_PCM_OUT, 59 GND11, 60 GND12, 61 GND13, 62 GND14

## NB679
designator U?
pins: 1 VIN, 2 DGND, 3 PG, 5 VOUT, 6 LDO, 7 SW, 8 BST, 9 VCC, 10 AGND, 11 EN, 12 ENLDO

## NMOS_0
designator Q?
footprint sot-23
pins: 1 GATE (in), 2 SOURCE (in), 3 DRAIN (in)

## NPN
designator Q?
pins: 1 BASE, 2 EMITTER, 3 COLLECTOR

## NPN_1
designator Q?
pins: 1 BASE (in), 2 EMITTER, 3 COLLECT

## PCF8563_0
designator U?
footprint SOP-8
pins: 1 GND, 2 RF_IN, 3 GND, 4 GND, 5 GND, 6 +1.2V, 7 GND, 8 +3.3V, 9 GND, 10 1.8V, 11 GND, 12 BREST, 13 HOST_BUS0, 14 HOST_BUS1, 15 GND, 16 HOST_BUS2, 17 HOST_BUS3, 18 HOST_BUS4, 19 HOST_BUS5, 20 HOST_BUS6, 21 HOST_BUS7, 22 HOST_BUS8, 23 HOST_BUS9, 24 HOST_BUS10, 25 HOST_BUS11, 26 HOST_BUS12, 27 HOST_BUS13, 28 HOST_BUS14, 29 GND, 30 GND
1 alternate drawing of the same symbol

## PCF8563_1
designator U?
footprint SOP-8
pins: 1 GND, 2 RF_IN, 3 GND, 4 GND, 5 GND, 6 +1.2V, 7 GND, 8 +3.3V, 9 GND, 10 1.8V, 11 ADD, 12 BREST, 13 HOST_BUS0, 14 HOST_BUS1, 15 GND, 16 HOST_BUS2, 17 HOST_BUS3, 18 HOST_BUS4, 19 HOST_BUS5, 20 HOST_BUS6, 21 HOST_BUS7, 22 HOST_BUS8, 23 HOST_BUS9, 24 HOST_BUS10, 25 HOST_BUS11, 26 HOST_BUS12, 27 HOST_BUS13, 28 HOST_BUS14, 29 GND, 30 GND
1 alternate drawing of the same symbol

## PCIeX4_0
designator U?
pins: 1 G1, 2 G2, A1 PRSNT1#, A2 +12V_4, A3 +12V_5, A4 GND_A4, A5 JTAG_TCK, A6 JTAG_TDI, A7 JTAG_TDO, A8 JTAG_TMS, A9 +3.3V_2, A10 +3.3V_3, A11 PERST#, A12 GND_A12, A13 REFCLK+, A14 REFCLK-, A15 GND_A15, A16 PERp0, A17 PERn0, A18 GND_A18, A19 RSVD_A19, A20 GND_A20, A21 PERp1, A22 PERn1, A23 GND_A23, A24 GND_A24, A25 PERp2, A26 PERn2, A27 GND_A27, A28 GND_A28, A29 PERp3, A30 PERn3, A31 GND_A31, A32 RSVD_A32, B1 +12V_1, B2 +12V_2, B3 +12V_3, B4 GND_B4, B5 SMCLK, B6 SMDAT, B7 GND_B7, B8 +3.3V_1, B9 JTAG_TRST, B10 3.3VAUX, B11 WAKE#, B12 RSVD_B12, B13 GND_B13, B14 PETp0, B15 PETn0, B16 GND_B16, B17 PRSNT2#_1, B18 GND_B18, B19 PETp1, B20 PETn1, B21 GND_B21, B22 GND_B22, B23 PETp2, B24 PETn2, B25 GND_B25, B26 GND_B26, B27 PETp3, B28 PETn3, B29 GND_B29, B30 RSVD_B30, B31 PRSNT2#_2, B32 GND_B32

## PHONEJACK STEREO SW_0
designator J?
pins: 1 HP, 2 COM, 3 L, 4 R

## PHONEJACK STEREO SW_1
designator J?
footprint PHONE-ST-0166MT-050
pins: 1 R, 2 COM, 3 HP, 4 L, 5

## PHONEJACK STEREO SW_2
designator J?
pins: 1 E, 2, 3 A, 4 D, 5 B, 6 C

## PHONEJACK STEREO SW_3
designator J?
pins: 1, 2 E, 3 A, 4 D, 5 B, 6 C

## PHONEJACK STEREO SW_4
designator J?
pins: 2, 3, 4, 5, 6, 7

## PI6C557-05BLE_0
designator U?
footprint TSSOP20
pins: 1 VDDXD, 2 S0, 3 S1, 4 S2, 5 X1, 6 X2, 7 PDn, 8 OE, 9 GNDXD, 10 IREF, 11 CLK3N, 12 CLK3P, 13 CLK2N, 14 CLK2P, 15 VDDODA, 16 GNDODA, 17 CLK1N, 18 CLK1P, 19 CLK0N, 20 CLK0P

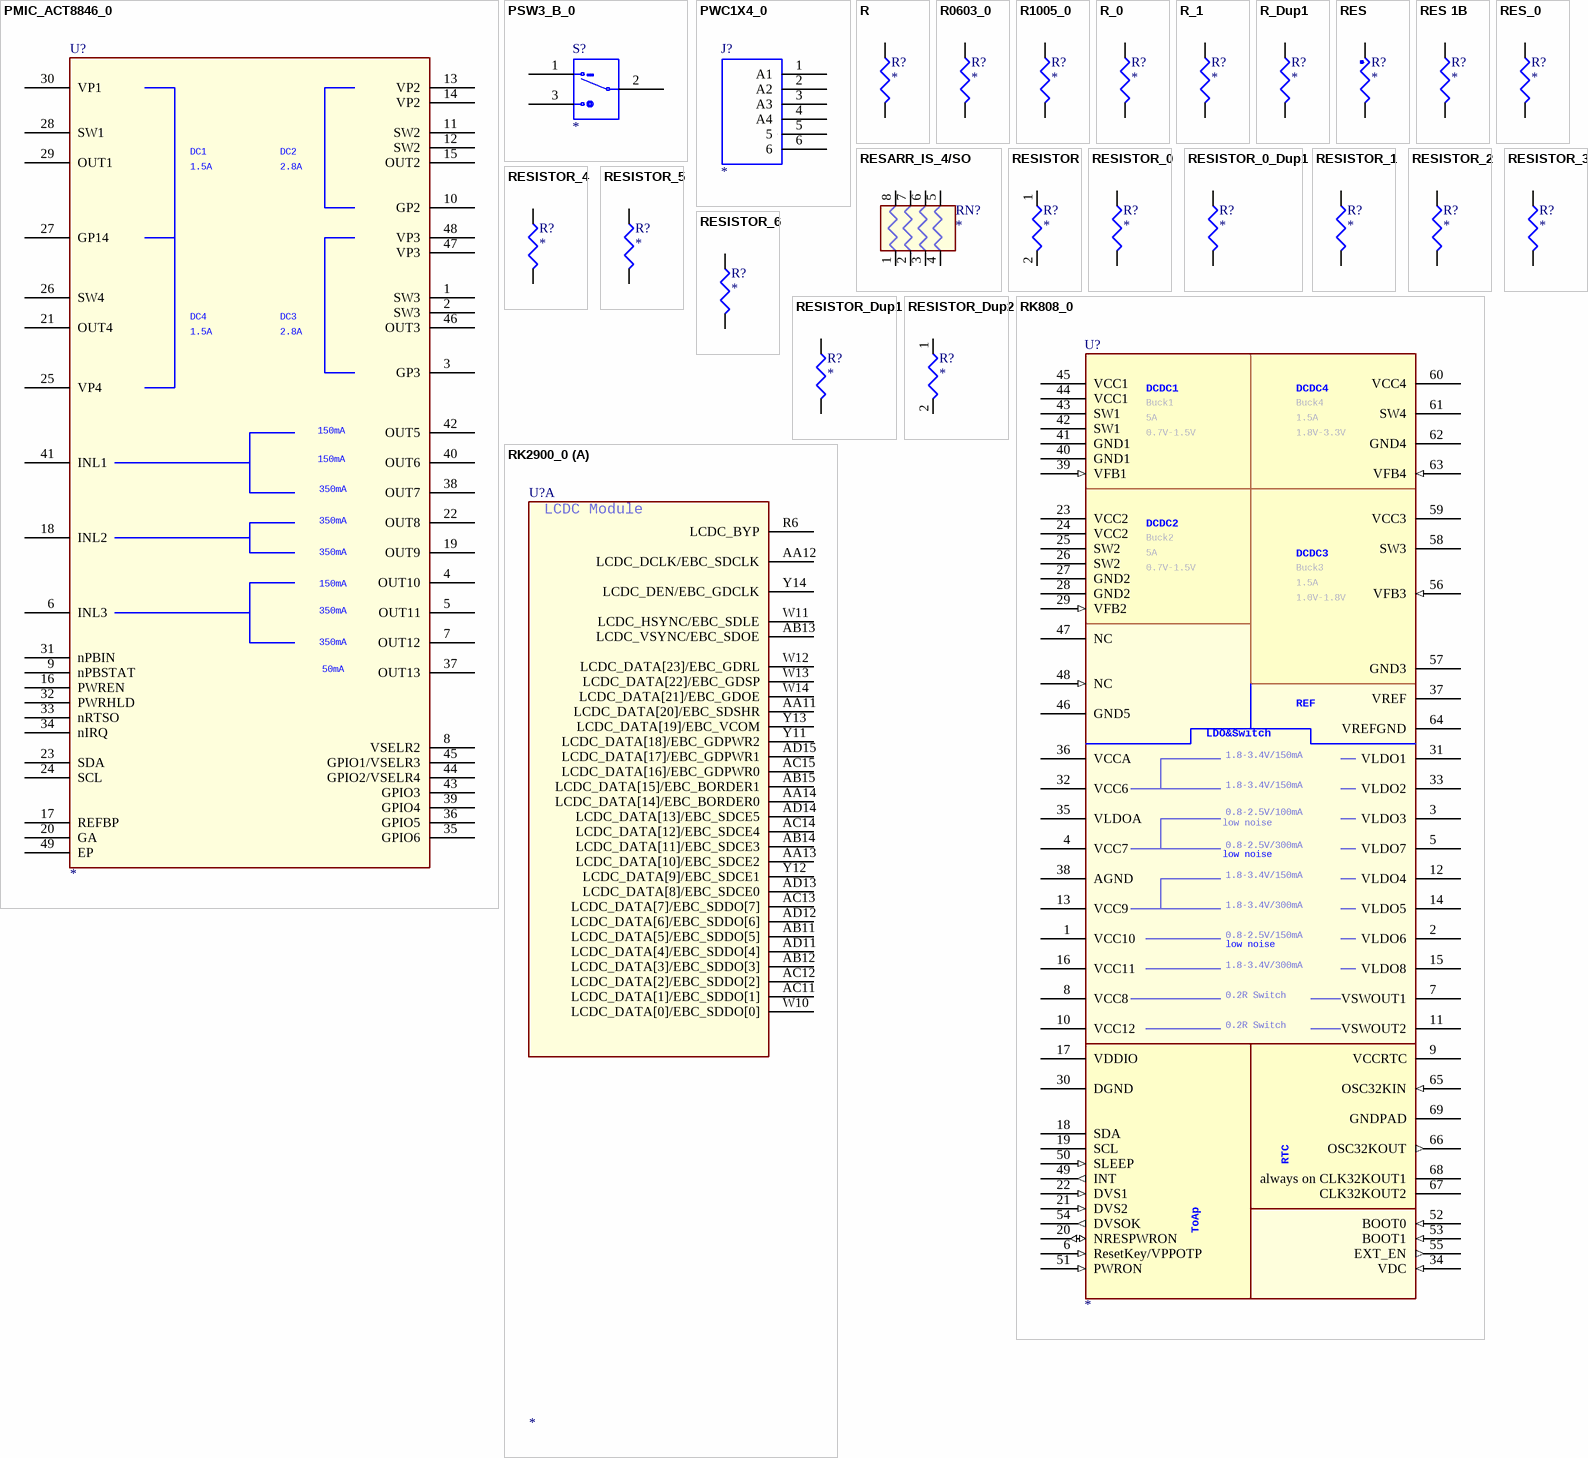
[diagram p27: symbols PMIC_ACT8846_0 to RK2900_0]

## PMIC_ACT8846_0
designator U?
footprint QFN48-6X6
pins: 1 SW3 (power), 2 SW3 (power), 3 GP3, 4 OUT10, 5 OUT11, 6 INL3, 7 OUT12, 8 VSELR2, 9 nPBSTAT, 10 GP2, 11 SW2 (power), 12 SW2 (power), 13 VP2 (power), 14 VP2 (power), 15 OUT2, 16 PWREN, 17 REFBP, 18 INL2, 19 OUT9, 20 GA, 21 OUT4, 22 OUT8, 23 SDA, 24 SCL, 25 VP4, 26 SW4, 27 GP14, 28 SW1, 29 OUT1, 30 VP1, 31 nPBIN, 32 PWRHLD, 33 nRTSO, 34 nIRQ, 35 GPIO6, 36 GPIO5, 37 OUT13, 38 OUT7, 39 GPIO4, 40 OUT6, 41 INL1, 42 OUT5, 43 GPIO3, 44 GPIO2/VSELR4, 45 GPIO1/VSELR3, 46 OUT3, 47 VP3 (power), 48 VP3 (power), 49 EP

## PSW3_B_0
designator S?
PARTS: 1; OriginalSymbolOrigin: (20,50); LEVEL: STD; DEVICE: BR-11C-11P6
pins: 1 P1, 2 P2, 3 P3

## PWC1X4_0
designator J?
PARTS: 1; OriginalSymbolOrigin: (0,70); PKG_TYPE: 4; LEVEL: STD; DEVICE: HEAD1X4
pins: 1 A1, 2 A2, 3 A3, 4 A4, 5, 6

## R
designator R?
pins: 1, 2

## R0603_0
designator R?
footprint R0603
pins: 1, 2

## R1005_0
designator R?
footprint R1005
pins: 1, 2

## R_0
designator R?
pins: 1, 2

## R_1
designator R?
pins: 1, 2

## R_Dup1
designator R?
pins: 1, 2

## RES
designator R?
CLASS: DISCRETE
pins: 1, 2

## RES 1B
designator R?
pins: 1, 2

## RES_0
designator R?
footprint R0603
pins: 1, 2

## RESARR_IS_4/SO
designator RN?
pins: 1, 2, 3, 4, 5, 6, 7, 8

## RESISTOR
designator R?
footprint R0402
pins: 1, 2

## RESISTOR_0
designator R?
pins: 1, 2

## RESISTOR_0_Dup1
designator R?
pins: 1, 2

## RESISTOR_1
designator R?
pins: 1, 2

## RESISTOR_2
designator R?
footprint R0402
pins: 1, 2

## RESISTOR_3
designator R?
footprint R0402
pins: 1, 2

## RESISTOR_4
designator R?
footprint R0402
pins: 1, 2

## RESISTOR_5
designator R?
footprint R0402
pins: 1, 2

## RESISTOR_6
designator R?
footprint R0402
pins: 1, 2

## RESISTOR_Dup1
designator R?
pins: 1, 2

## RESISTOR_Dup2
designator R?
footprint R0402
pins: 1, 2

## RK808_0
designator U?
pins: 1 VCC10 (power), 2 VLDO6 (power), 3 VLDO3 (power), 4 VCC7 (power), 5 VLDO7 (power), 6 ResetKey/VPPOTP (in), 7 VSWOUT1 (power), 8 VCC8 (power), 9 VCCRTC (power), 10 VCC12 (power), 11 VSWOUT2 (power), 12 VLDO4 (power), 13 VCC9 (power), 14 VLDO5 (power), 15 VLDO8 (power), 16 VCC11 (power), 17 VDDIO (power), 18 SDA (oc), 19 SCL (oc), 20 NRESPWRON (io), 21 DVS2 (in), 22 DVS1 (in), 23 VCC2 (power), 24 VCC2 (power), 25 SW2 (power), 26 SW2 (power), 27 GND2 (power), 28 GND2 (power), 29 VFB2 (in), 30 DGND (power), 31 VLDO1 (power), 32 VCC6 (power), 33 VLDO2 (power), 34 VDC (in), 35 VLDOA (power), 36 VCCA (power), 37 VREF (power), 38 AGND (power), 39 VFB1 (in), 40 GND1 (power), 41 GND1 (power), 42 SW1 (power), 43 SW1 (power), 44 VCC1 (power), 45 VCC1 (power), 46 GND5 (power), 47 NC (hiz), 48 NC (in), 49 INT (out), 50 SLEEP (in), 51 PWRON (in), 52 BOOT0 (in), 53 BOOT1 (in), 54 DVSOK (out), 55 EXT_EN (out), 56 VFB3 (in), 57 GND3 (power), 58 SW3 (power), 59 VCC3 (power), 60 VCC4 (power), 61 SW4 (power), 62 GND4 (power), 63 VFB4 (in), 64 VREFGND (power), 65 OSC32KIN (in), 66 OSC32KOUT (out), 67 CLK32KOUT2 (oc), 68 always on CLK32KOUT1 (oc), 69 GNDPAD (power)

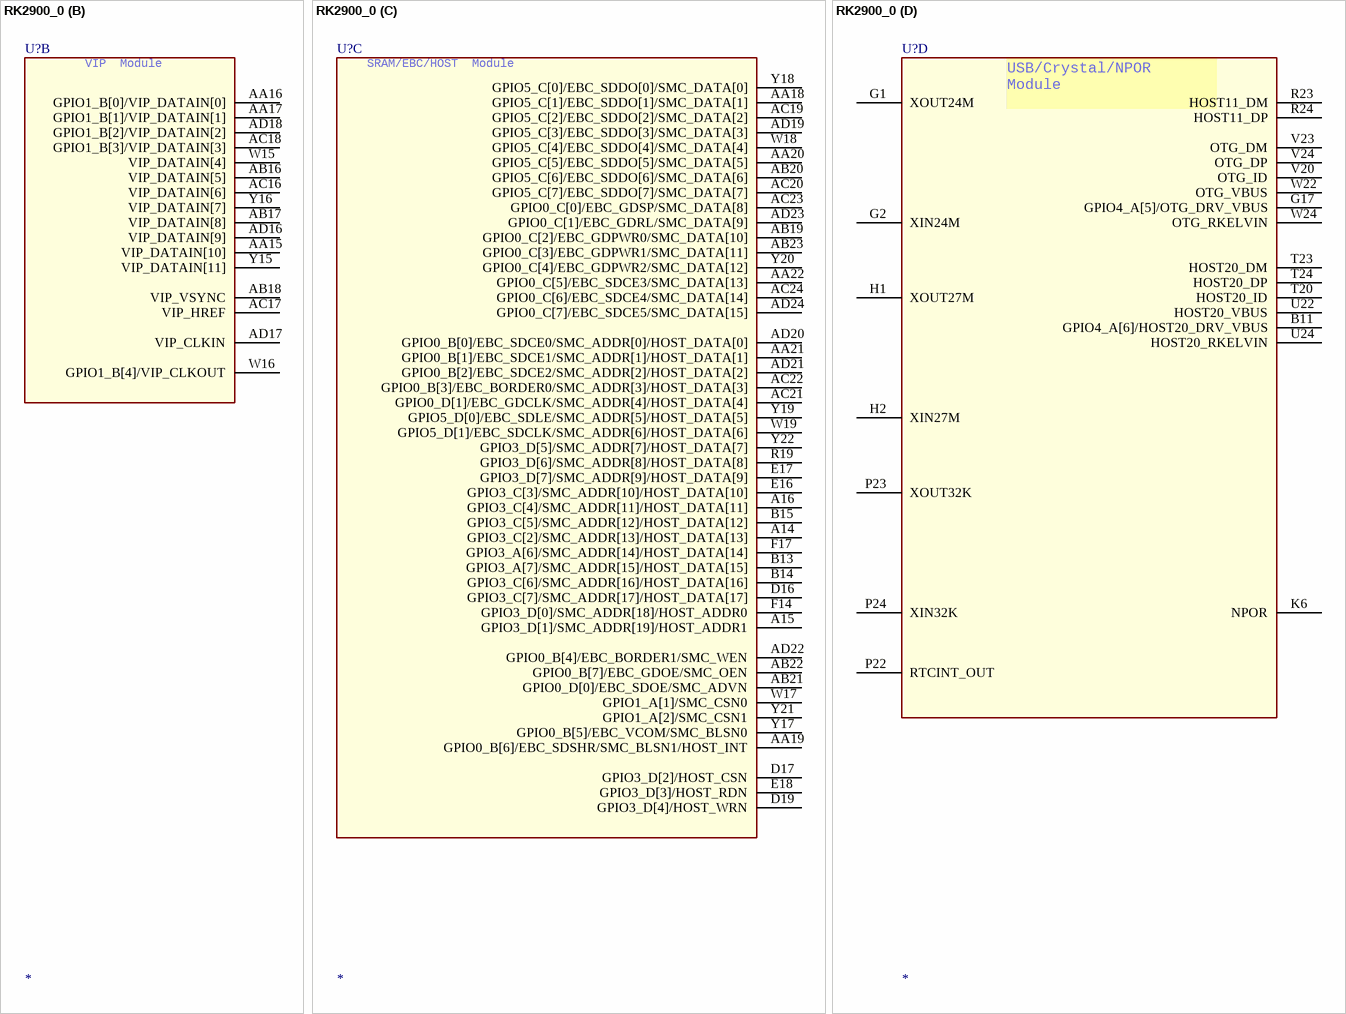
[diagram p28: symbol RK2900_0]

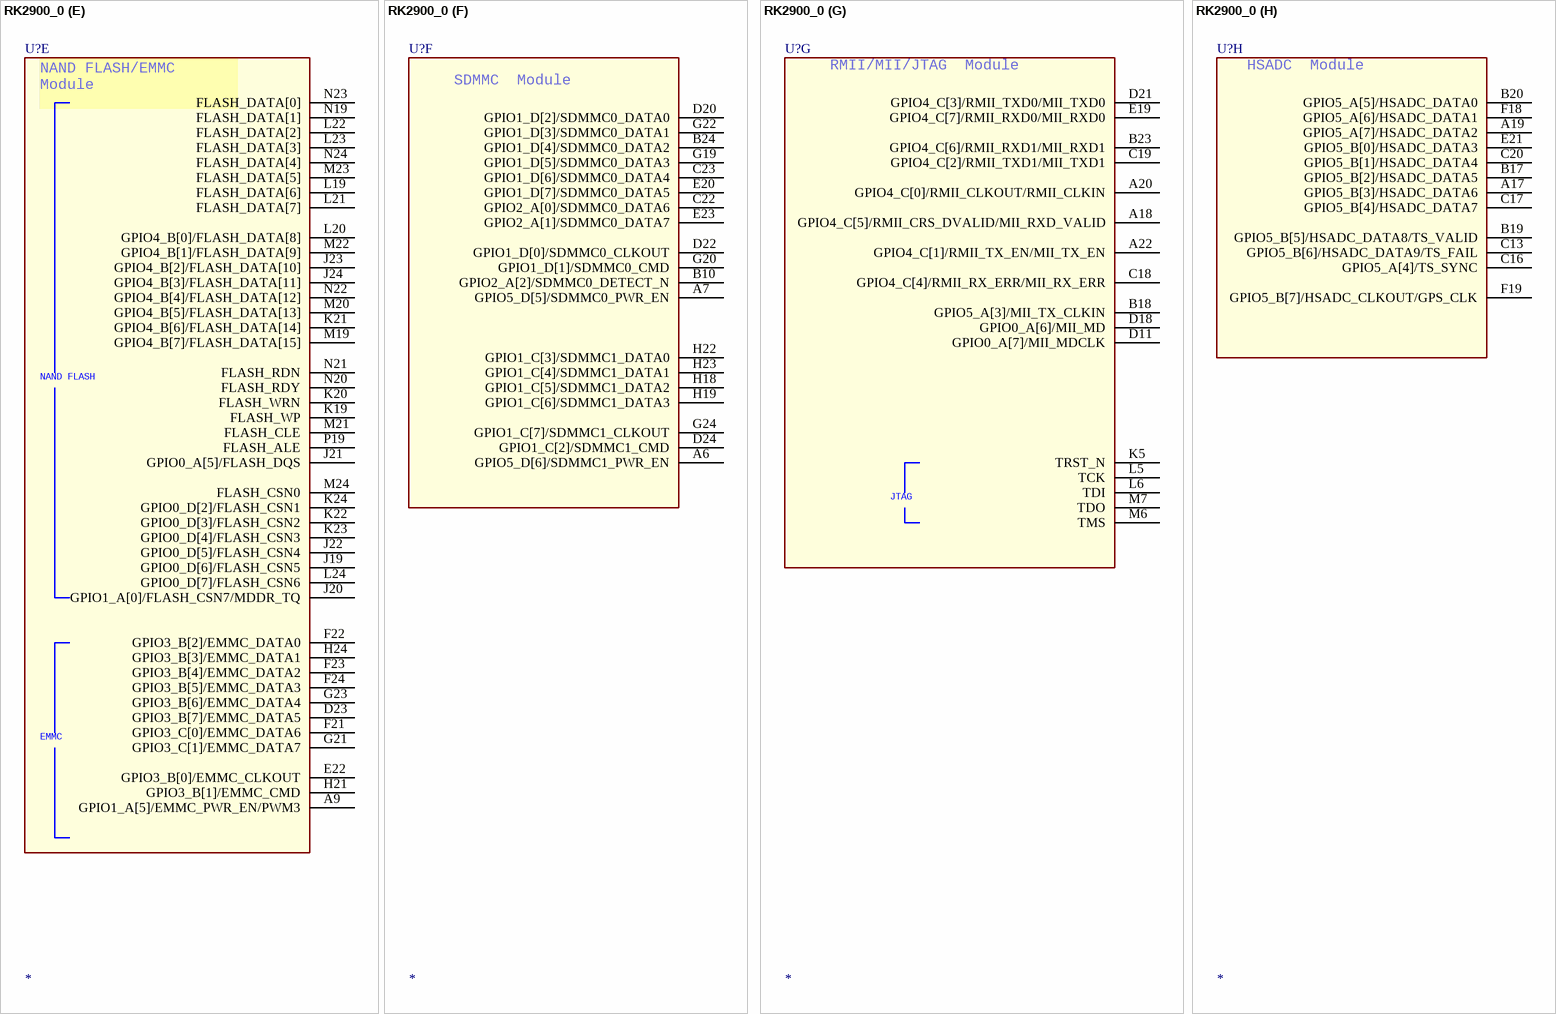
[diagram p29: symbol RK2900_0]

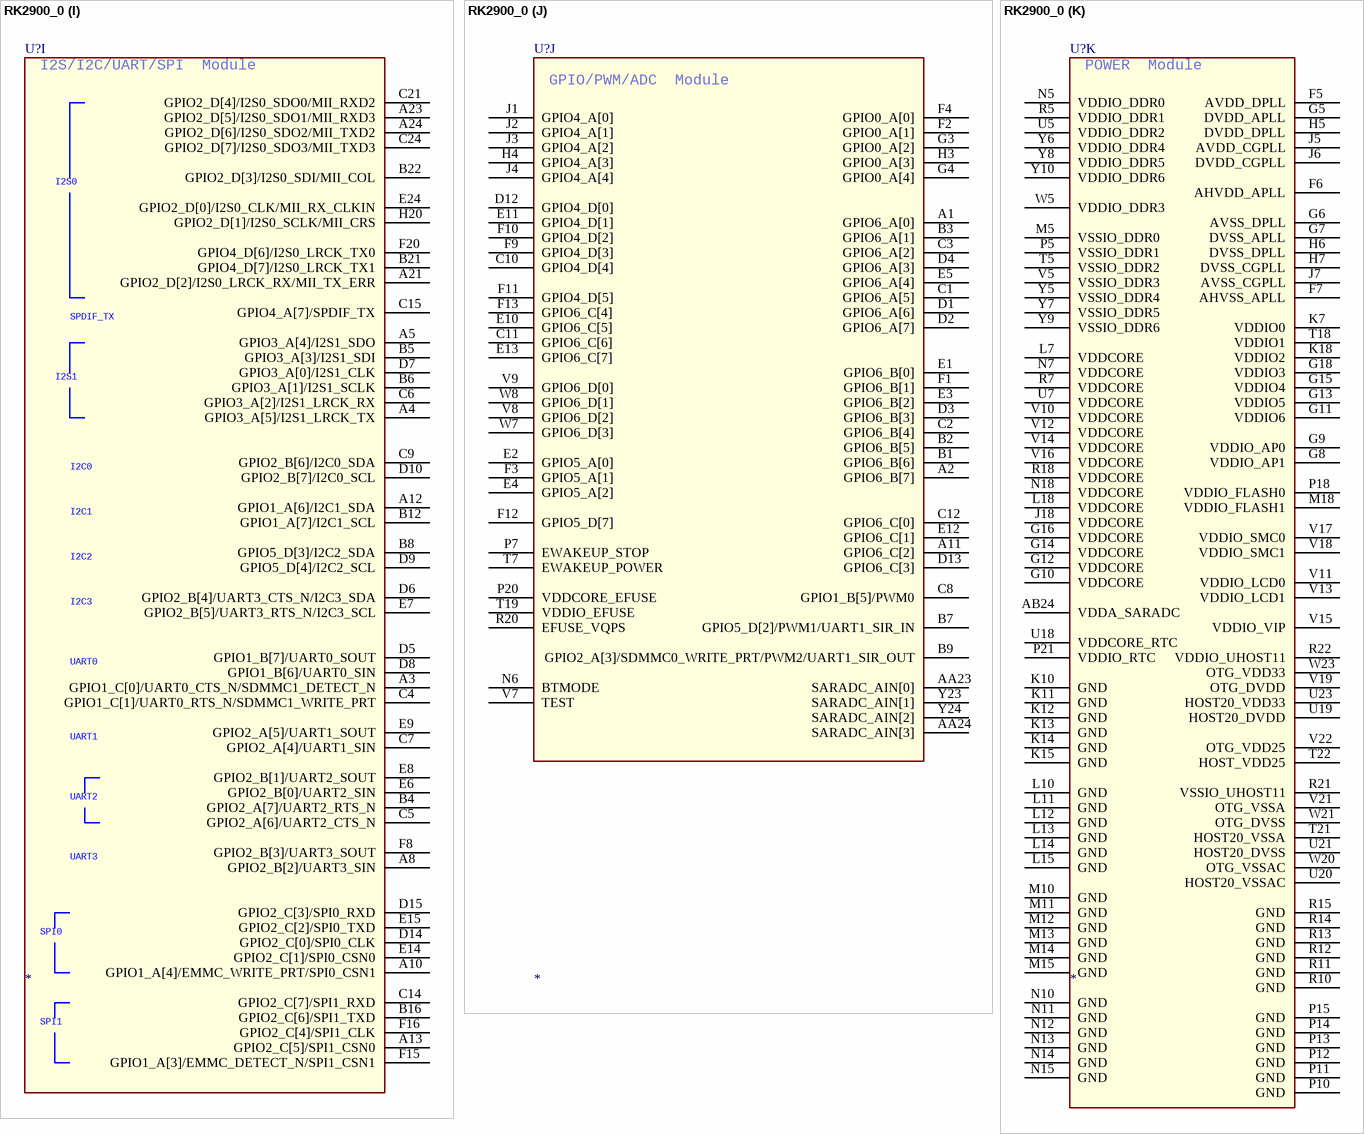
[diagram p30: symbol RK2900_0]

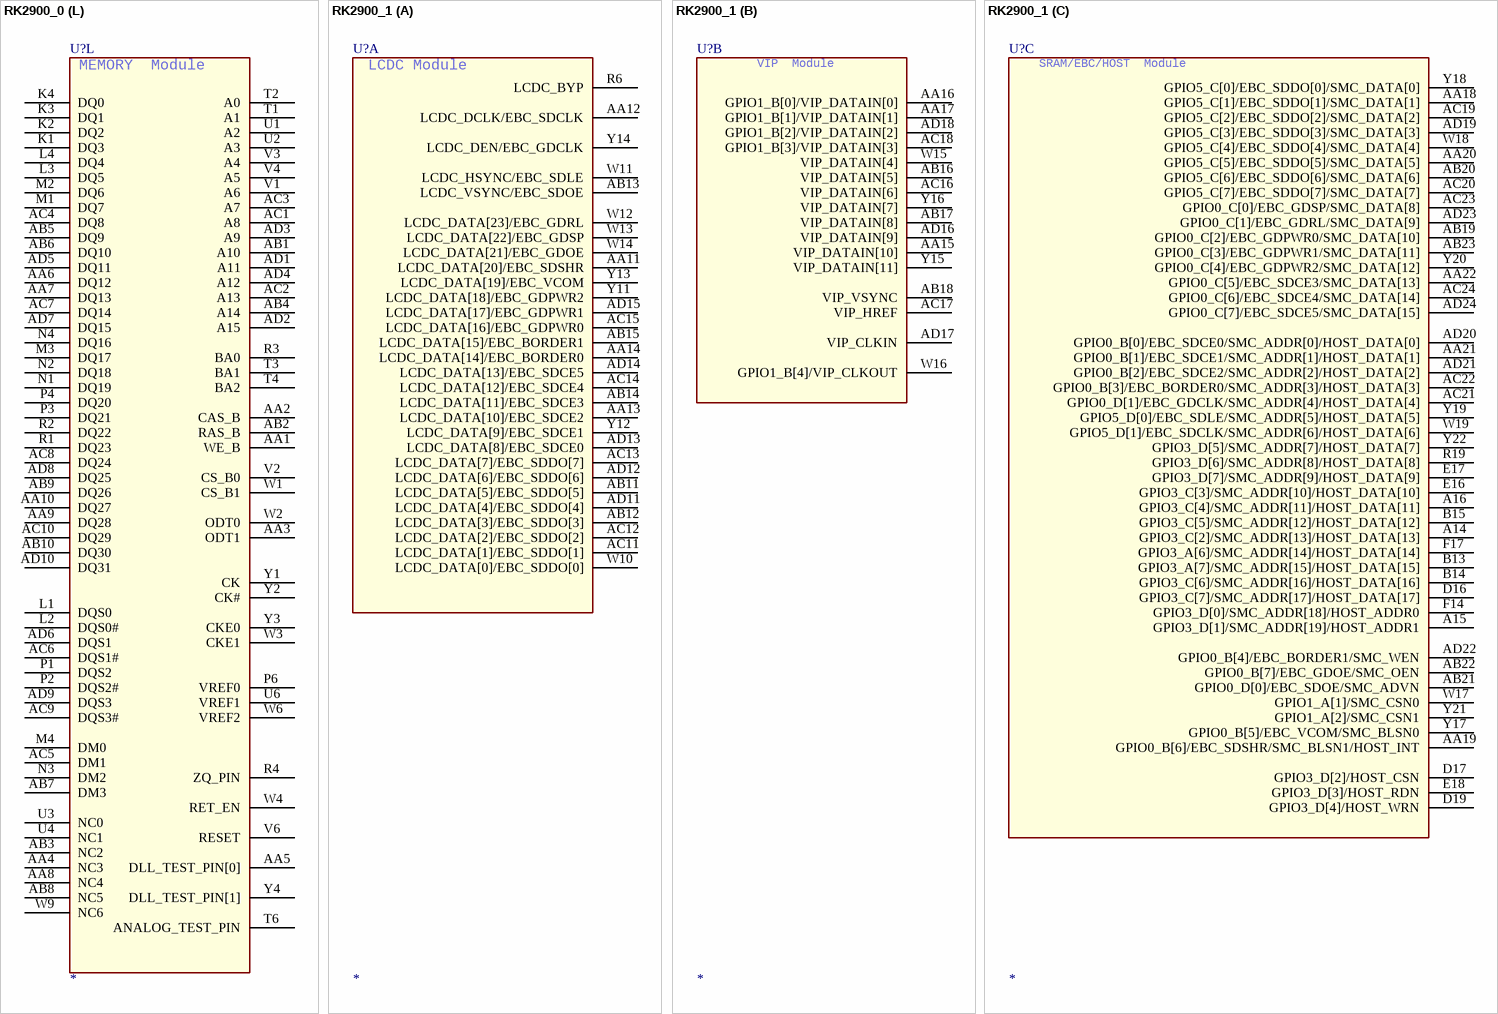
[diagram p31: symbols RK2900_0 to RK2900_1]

## RK2900_0
designator U?
footprint BGA512
part A pins: AA11 LCDC_DATA[20]/EBC_SDSHR, AA12 LCDC_DCLK/EBC_SDCLK, AA13 LCDC_DATA[10]/EBC_SDCE2, AA14 LCDC_DATA[14]/EBC_BORDER0, AB11 LCDC_DATA[5]/EBC_SDDO[5], AB12 LCDC_DATA[3]/EBC_SDDO[3], AB13 LCDC_VSYNC/EBC_SDOE, AB14 LCDC_DATA[11]/EBC_SDCE3, AB15 LCDC_DATA[15]/EBC_BORDER1, AC11 LCDC_DATA[1]/EBC_SDDO[1], AC12 LCDC_DATA[2]/EBC_SDDO[2], AC13 LCDC_DATA[7]/EBC_SDDO[7], AC14 LCDC_DATA[12]/EBC_SDCE4, AC15 LCDC_DATA[16]/EBC_GDPWR0, AD11 LCDC_DATA[4]/EBC_SDDO[4], AD12 LCDC_DATA[6]/EBC_SDDO[6], AD13 LCDC_DATA[8]/EBC_SDCE0, AD14 LCDC_DATA[13]/EBC_SDCE5, AD15 LCDC_DATA[17]/EBC_GDPWR1, R6 LCDC_BYP, W10 LCDC_DATA[0]/EBC_SDDO[0], W11 LCDC_HSYNC/EBC_SDLE, W12 LCDC_DATA[23]/EBC_GDRL, W13 LCDC_DATA[22]/EBC_GDSP, W14 LCDC_DATA[21]/EBC_GDOE, Y11 LCDC_DATA[18]/EBC_GDPWR2, Y12 LCDC_DATA[9]/EBC_SDCE1, Y13 LCDC_DATA[19]/EBC_VCOM, Y14 LCDC_DEN/EBC_GDCLK
part B pins: AA15 VIP_DATAIN[10], AA16 GPIO1_B[0]/VIP_DATAIN[0], AA17 GPIO1_B[1]/VIP_DATAIN[1], AB16 VIP_DATAIN[5], AB17 VIP_DATAIN[8], AB18 VIP_VSYNC, AC16 VIP_DATAIN[6], AC17 VIP_HREF, AC18 GPIO1_B[3]/VIP_DATAIN[3], AD16 VIP_DATAIN[9], AD17 VIP_CLKIN, AD18 GPIO1_B[2]/VIP_DATAIN[2], W15 VIP_DATAIN[4], W16 GPIO1_B[4]/VIP_CLKOUT, Y15 VIP_DATAIN[11], Y16 VIP_DATAIN[7]
part C pins: A14 GPIO3_C[2]/SMC_ADDR[13]/HOST_DATA[13], A15 GPIO3_D[1]/SMC_ADDR[19]/HOST_ADDR1, A16 GPIO3_C[4]/SMC_ADDR[11]/HOST_DATA[11], AA18 GPIO5_C[1]/EBC_SDDO[1]/SMC_DATA[1], AA19 GPIO0_B[6]/EBC_SDSHR/SMC_BLSN1/HOST_INT, AA20 GPIO5_C[5]/EBC_SDDO[5]/SMC_DATA[5], AA21 GPIO0_B[1]/EBC_SDCE1/SMC_ADDR[1]/HOST_DATA[1], AA22 GPIO0_C[5]/EBC_SDCE3/SMC_DATA[13], AB19 GPIO0_C[2]/EBC_GDPWR0/SMC_DATA[10], AB20 GPIO5_C[6]/EBC_SDDO[6]/SMC_DATA[6], AB21 GPIO0_D[0]/EBC_SDOE/SMC_ADVN, AB22 GPIO0_B[7]/EBC_GDOE/SMC_OEN, AB23 GPIO0_C[3]/EBC_GDPWR1/SMC_DATA[11], AC19 GPIO5_C[2]/EBC_SDDO[2]/SMC_DATA[2], AC20 GPIO5_C[7]/EBC_SDDO[7]/SMC_DATA[7], AC21 GPIO0_D[1]/EBC_GDCLK/SMC_ADDR[4]/HOST_DATA[4], AC22 GPIO0_B[3]/EBC_BORDER0/SMC_ADDR[3]/HOST_DATA[3], AC23 GPIO0_C[0]/EBC_GDSP/SMC_DATA[8], AC24 GPIO0_C[6]/EBC_SDCE4/SMC_DATA[14], AD19 GPIO5_C[3]/EBC_SDDO[3]/SMC_DATA[3], AD20 GPIO0_B[0]/EBC_SDCE0/SMC_ADDR[0]/HOST_DATA[0], AD21 GPIO0_B[2]/EBC_SDCE2/SMC_ADDR[2]/HOST_DATA[2], AD22 GPIO0_B[4]/EBC_BORDER1/SMC_WEN, AD23 GPIO0_C[1]/EBC_GDRL/SMC_DATA[9], AD24 GPIO0_C[7]/EBC_SDCE5/SMC_DATA[15], B13 GPIO3_A[7]/SMC_ADDR[15]/HOST_DATA[15], B14 GPIO3_C[6]/SMC_ADDR[16]/HOST_DATA[16], B15 GPIO3_C[5]/SMC_ADDR[12]/HOST_DATA[12], D16 GPIO3_C[7]/SMC_ADDR[17]/HOST_DATA[17], D17 GPIO3_D[2]/HOST_CSN, D19 GPIO3_D[4]/HOST_WRN, E16 GPIO3_C[3]/SMC_ADDR[10]/HOST_DATA[10], E17 GPIO3_D[7]/SMC_ADDR[9]/HOST_DATA[9], E18 GPIO3_D[3]/HOST_RDN, F14 GPIO3_D[0]/SMC_ADDR[18]/HOST_ADDR0, F17 GPIO3_A[6]/SMC_ADDR[14]/HOST_DATA[14], R19 GPIO3_D[6]/SMC_ADDR[8]/HOST_DATA[8], W17 GPIO1_A[1]/SMC_CSN0, W18 GPIO5_C[4]/EBC_SDDO[4]/SMC_DATA[4], W19 GPIO5_D[1]/EBC_SDCLK/SMC_ADDR[6]/HOST_DATA[6], Y17 GPIO0_B[5]/EBC_VCOM/SMC_BLSN0, Y18 GPIO5_C[0]/EBC_SDDO[0]/SMC_DATA[0], Y19 GPIO5_D[0]/EBC_SDLE/SMC_ADDR[5]/HOST_DATA[5], Y20 GPIO0_C[4]/EBC_GDPWR2/SMC_DATA[12], Y21 GPIO1_A[2]/SMC_CSN1, Y22 GPIO3_D[5]/SMC_ADDR[7]/HOST_DATA[7]
part D pins: B11 GPIO4_A[6]/HOST20_DRV_VBUS, G1 XOUT24M, G2 XIN24M, G17 GPIO4_A[5]/OTG_DRV_VBUS, H1 XOUT27M, H2 XIN27M, K6 NPOR, P22 RTCINT_OUT, P23 XOUT32K, P24 XIN32K, R23 HOST11_DM, R24 HOST11_DP, T20 HOST20_ID, T23 HOST20_DM, T24 HOST20_DP, U22 HOST20_VBUS, U24 HOST20_RKELVIN, V20 OTG_ID, V23 OTG_DM, V24 OTG_DP, W22 OTG_VBUS, W24 OTG_RKELVIN
part E pins: A9 GPIO1_A[5]/EMMC_PWR_EN/PWM3, D23 GPIO3_B[7]/EMMC_DATA5, E22 GPIO3_B[0]/EMMC_CLKOUT, F21 GPIO3_C[0]/EMMC_DATA6, F22 GPIO3_B[2]/EMMC_DATA0, F23 GPIO3_B[4]/EMMC_DATA2, F24 GPIO3_B[5]/EMMC_DATA3, G21 GPIO3_C[1]/EMMC_DATA7, G23 GPIO3_B[6]/EMMC_DATA4, H21 GPIO3_B[1]/EMMC_CMD, H24 GPIO3_B[3]/EMMC_DATA1, J19 GPIO0_D[6]/FLASH_CSN5, J20 GPIO1_A[0]/FLASH_CSN7/MDDR_TQ, J21 GPIO0_A[5]/FLASH_DQS, J22 GPIO0_D[5]/FLASH_CSN4, J23 GPIO4_B[2]/FLASH_DATA[10], J24 GPIO4_B[3]/FLASH_DATA[11], K19 FLASH_WP, K20 FLASH_WRN, K21 GPIO4_B[6]/FLASH_DATA[14], K22 GPIO0_D[3]/FLASH_CSN2, K23 GPIO0_D[4]/FLASH_CSN3, K24 GPIO0_D[2]/FLASH_CSN1, L19 FLASH_DATA[6], L20 GPIO4_B[0]/FLASH_DATA[8], L21 FLASH_DATA[7], L22 FLASH_DATA[2], L23 FLASH_DATA[3], L24 GPIO0_D[7]/FLASH_CSN6, M19 GPIO4_B[7]/FLASH_DATA[15], M20 GPIO4_B[5]/FLASH_DATA[13], M21 FLASH_CLE, M22 GPIO4_B[1]/FLASH_DATA[9], M23 FLASH_DATA[5], M24 FLASH_CSN0, N19 FLASH_DATA[1], N20 FLASH_RDY, N21 FLASH_RDN, N22 GPIO4_B[4]/FLASH_DATA[12], N23 FLASH_DATA[0], N24 FLASH_DATA[4], P19 FLASH_ALE
part F pins: A6 GPIO5_D[6]/SDMMC1_PWR_EN, A7 GPIO5_D[5]/SDMMC0_PWR_EN, B10 GPIO2_A[2]/SDMMC0_DETECT_N, B24 GPIO1_D[4]/SDMMC0_DATA2, C22 GPIO2_A[0]/SDMMC0_DATA6, C23 GPIO1_D[6]/SDMMC0_DATA4, D20 GPIO1_D[2]/SDMMC0_DATA0, D22 GPIO1_D[0]/SDMMC0_CLKOUT, D24 GPIO1_C[2]/SDMMC1_CMD, E20 GPIO1_D[7]/SDMMC0_DATA5, E23 GPIO2_A[1]/SDMMC0_DATA7, G19 GPIO1_D[5]/SDMMC0_DATA3, G20 GPIO1_D[1]/SDMMC0_CMD, G22 GPIO1_D[3]/SDMMC0_DATA1, G24 GPIO1_C[7]/SDMMC1_CLKOUT, H18 GPIO1_C[5]/SDMMC1_DATA2, H19 GPIO1_C[6]/SDMMC1_DATA3, H22 GPIO1_C[3]/SDMMC1_DATA0, H23 GPIO1_C[4]/SDMMC1_DATA1
part G pins: A18 GPIO4_C[5]/RMII_CRS_DVALID/MII_RXD_VALID, A20 GPIO4_C[0]/RMII_CLKOUT/RMII_CLKIN, A22 GPIO4_C[1]/RMII_TX_EN/MII_TX_EN, B18 GPIO5_A[3]/MII_TX_CLKIN, B23 GPIO4_C[6]/RMII_RXD1/MII_RXD1, C18 GPIO4_C[4]/RMII_RX_ERR/MII_RX_ERR, C19 GPIO4_C[2]/RMII_TXD1/MII_TXD1, D11 GPIO0_A[7]/MII_MDCLK, D18 GPIO0_A[6]/MII_MD, D21 GPIO4_C[3]/RMII_TXD0/MII_TXD0, E19 GPIO4_C[7]/RMII_RXD0/MII_RXD0, K5 TRST_N, L5 TCK, L6 TDI, M6 TMS, M7 TDO
part H pins: A17 GPIO5_B[3]/HSADC_DATA6, A19 GPIO5_A[7]/HSADC_DATA2, B17 GPIO5_B[2]/HSADC_DATA5, B19 GPIO5_B[5]/HSADC_DATA8/TS_VALID, B20 GPIO5_A[5]/HSADC_DATA0, C13 GPIO5_B[6]/HSADC_DATA9/TS_FAIL, C16 GPIO5_A[4]/TS_SYNC, C17 GPIO5_B[4]/HSADC_DATA7, C20 GPIO5_B[1]/HSADC_DATA4, E21 GPIO5_B[0]/HSADC_DATA3, F18 GPIO5_A[6]/HSADC_DATA1, F19 GPIO5_B[7]/HSADC_CLKOUT/GPS_CLK
part I pins: A3 GPIO1_C[0]/UART0_CTS_N/SDMMC1_DETECT_N, A4 GPIO3_A[5]/I2S1_LRCK_TX, A5 GPIO3_A[4]/I2S1_SDO, A8 GPIO2_B[2]/UART3_SIN, A10 GPIO1_A[4]/EMMC_WRITE_PRT/SPI0_CSN1, A12 GPIO1_A[6]/I2C1_SDA, A13 GPIO2_C[5]/SPI1_CSN0, A21 GPIO2_D[2]/I2S0_LRCK_RX/MII_TX_ERR, A23 GPIO2_D[5]/I2S0_SDO1/MII_RXD3, A24 GPIO2_D[6]/I2S0_SDO2/MII_TXD2, B4 GPIO2_A[7]/UART2_RTS_N, B5 GPIO3_A[3]/I2S1_SDI, B6 GPIO3_A[1]/I2S1_SCLK, B8 GPIO5_D[3]/I2C2_SDA, B12 GPIO1_A[7]/I2C1_SCL, B16 GPIO2_C[6]/SPI1_TXD, B21 GPIO4_D[7]/I2S0_LRCK_TX1, B22 GPIO2_D[3]/I2S0_SDI/MII_COL, C4 GPIO1_C[1]/UART0_RTS_N/SDMMC1_WRITE_PRT, C5 GPIO2_A[6]/UART2_CTS_N, C6 GPIO3_A[2]/I2S1_LRCK_RX, C7 GPIO2_A[4]/UART1_SIN, C9 GPIO2_B[6]/I2C0_SDA, C14 GPIO2_C[7]/SPI1_RXD, C15 GPIO4_A[7]/SPDIF_TX, C21 GPIO2_D[4]/I2S0_SDO0/MII_RXD2, C24 GPIO2_D[7]/I2S0_SDO3/MII_TXD3, D5 GPIO1_B[7]/UART0_SOUT, D6 GPIO2_B[4]/UART3_CTS_N/I2C3_SDA, D7 GPIO3_A[0]/I2S1_CLK, D8 GPIO1_B[6]/UART0_SIN, D9 GPIO5_D[4]/I2C2_SCL, D10 GPIO2_B[7]/I2C0_SCL, D14 GPIO2_C[0]/SPI0_CLK, D15 GPIO2_C[3]/SPI0_RXD, E6 GPIO2_B[0]/UART2_SIN, E7 GPIO2_B[5]/UART3_RTS_N/I2C3_SCL, E8 GPIO2_B[1]/UART2_SOUT, E9 GPIO2_A[5]/UART1_SOUT, E14 GPIO2_C[1]/SPI0_CSN0, E15 GPIO2_C[2]/SPI0_TXD, E24 GPIO2_D[0]/I2S0_CLK/MII_RX_CLKIN, F8 GPIO2_B[3]/UART3_SOUT, F15 GPIO1_A[3]/EMMC_DETECT_N/SPI1_CSN1, F16 GPIO2_C[4]/SPI1_CLK, F20 GPIO4_D[6]/I2S0_LRCK_TX0, H20 GPIO2_D[1]/I2S0_SCLK/MII_CRS
part J pins: A1 GPIO6_A[0], A2 GPIO6_B[7], A11 GPIO6_C[2], AA23 SARADC_AIN[0], AA24 SARADC_AIN[3], B1 GPIO6_B[6], B2 GPIO6_B[5], B3 GPIO6_A[1], B7 GPIO5_D[2]/PWM1/UART1_SIR_IN, B9 GPIO2_A[3]/SDMMC0_WRITE_PRT/PWM2/UART1_SIR_OUT, C1 GPIO6_A[5], C2 GPIO6_B[4], C3 GPIO6_A[2], C8 GPIO1_B[5]/PWM0, C10 GPIO4_D[4], C11 GPIO6_C[6], C12 GPIO6_C[0], D1 GPIO6_A[6], D2 GPIO6_A[7], D3 GPIO6_B[3], D4 GPIO6_A[3], D12 GPIO4_D[0], D13 GPIO6_C[3], E1 GPIO6_B[0], E2 GPIO5_A[0], E3 GPIO6_B[2], E4 GPIO5_A[2], E5 GPIO6_A[4], E10 GPIO6_C[5], E11 GPIO4_D[1], E12 GPIO6_C[1], E13 GPIO6_C[7], F1 GPIO6_B[1], F2 GPIO0_A[1], F3 GPIO5_A[1], F4 GPIO0_A[0], F9 GPIO4_D[3], F10 GPIO4_D[2], F11 GPIO4_D[5], F12 GPIO5_D[7], F13 GPIO6_C[4], G3 GPIO0_A[2], G4 GPIO0_A[4], H3 GPIO0_A[3], H4 GPIO4_A[3], J1 GPIO4_A[0], J2 GPIO4_A[1], J3 GPIO4_A[2], J4 GPIO4_A[4], N6 BTMODE, P7 EWAKEUP_STOP, P20 VDDCORE_EFUSE, R20 EFUSE_VQPS, T7 EWAKEUP_POWER, T19 VDDIO_EFUSE, V7 TEST, V8 GPIO6_D[2], V9 GPIO6_D[0], W7 GPIO6_D[3], W8 GPIO6_D[1], Y23 SARADC_AIN[1], Y24 SARADC_AIN[2]
part K pins: AB24 VDDA_SARADC, F5 AVDD_DPLL, F6 AHVDD_APLL, F7 AHVSS_APLL, G5 DVDD_APLL, G6 AVSS_DPLL, G7 DVSS_APLL, G8 VDDIO_AP1, G9 VDDIO_AP0, G10 VDDCORE, G11 VDDIO6, G12 VDDCORE, G13 VDDIO5, G14 VDDCORE, G15 VDDIO4, G16 VDDCORE, G18 VDDIO3, H5 DVDD_DPLL, H6 DVSS_DPLL, H7 DVSS_CGPLL, J5 AVDD_CGPLL, J6 DVDD_CGPLL, J7 AVSS_CGPLL, J18 VDDCORE, K7 VDDIO0, K10 GND, K11 GND, K12 GND, K13 GND, K14 GND, K15 GND, K18 VDDIO2, L7 VDDCORE, L10 GND, L11 GND, L12 GND, L13 GND, L14 GND, L15 GND, L18 VDDCORE, M5 VSSIO_DDR0, M10 GND, M11 GND, M12 GND, M13 GND, M14 GND, M15 GND, M18 VDDIO_FLASH1, N5 VDDIO_DDR0, N7 VDDCORE, N10 GND, N11 GND, N12 GND, N13 GND, N14 GND, N15 GND, N18 VDDCORE, P5 VSSIO_DDR1, P10 GND, P11 GND, P12 GND, P13 GND, P14 GND, P15 GND, P18 VDDIO_FLASH0, P21 VDDIO_RTC, R5 VDDIO_DDR1, R7 VDDCORE, R10 GND, R11 GND, R12 GND, R13 GND, R14 GND, R15 GND, R18 VDDCORE, R21 VSSIO_UHOST11, R22 VDDIO_UHOST11, T5 VSSIO_DDR2, T18 VDDIO1, T21 HOST20_VSSA, T22 HOST_VDD25, U5 VDDIO_DDR2, U7 VDDCORE, U18 VDDCORE_RTC, U19 HOST20_DVDD, U20 HOST20_VSSAC, U21 HOST20_DVSS, U23 HOST20_VDD33, V5 VSSIO_DDR3, V10 VDDCORE, V11 VDDIO_LCD0, V12 VDDCORE, V13 VDDIO_LCD1, V14 VDDCORE, V15 VDDIO_VIP, V16 VDDCORE, V17 VDDIO_SMC0, V18 VDDIO_SMC1, V19 OTG_DVDD, V21 OTG_VSSA, V22 OTG_VDD25, W5 VDDIO_DDR3, W20 OTG_VSSAC, W21 OTG_DVSS, W23 OTG_VDD33, Y5 VSSIO_DDR4, Y6 VDDIO_DDR4, Y7 VSSIO_DDR5, Y8 VDDIO_DDR5, Y9 VSSIO_DDR6, Y10 VDDIO_DDR6
part L pins: AA1 WE_B, AA2 CAS_B, AA3 ODT1, AA4 NC3, AA5 DLL_TEST_PIN[0], AA6 DQ12, AA7 DQ13, AA8 NC4, AA9 DQ28, AA10 DQ27, AB1 A10, AB2 RAS_B, AB3 NC2, AB4 A14, AB5 DQ9, AB6 DQ10, AB7 DM3, AB8 NC5, AB9 DQ26, AB10 DQ30, AC1 A8, AC2 A13, AC3 A7, AC4 DQ8, AC5 DM1, AC6 DQS1#, AC7 DQ14, AC8 DQ24, AC9 DQS3#, AC10 DQ29, AD1 A11, AD2 A15, AD3 A9, AD4 A12, AD5 DQ11, AD6 DQS1, AD7 DQ15, AD8 DQ25, AD9 DQS3, AD10 DQ31, K1 DQ3, K2 DQ2, K3 DQ1, K4 DQ0, L1 DQS0, L2 DQS0#, L3 DQ5, L4 DQ4, M1 DQ7, M2 DQ6, M3 DQ17, M4 DM0, N1 DQ19, N2 DQ18, N3 DM2, N4 DQ16, P1 DQS2, P2 DQS2#, P3 DQ21, P4 DQ20, P6 VREF0, R1 DQ23, R2 DQ22, R3 BA0, R4 ZQ_PIN, T1 A1, T2 A0, T3 BA1, T4 BA2, T6 ANALOG_TEST_PIN, U1 A2, U2 A3, U3 NC0, U4 NC1, U6 VREF1, V1 A6, V2 CS_B0, V3 A4, V4 A5, V6 RESET, W1 CS_B1, W2 ODT0, W3 CKE1, W4 RET_EN, W6 VREF2, W9 NC6, Y1 CK, Y2 CK#, Y3 CKE0, Y4 DLL_TEST_PIN[1]

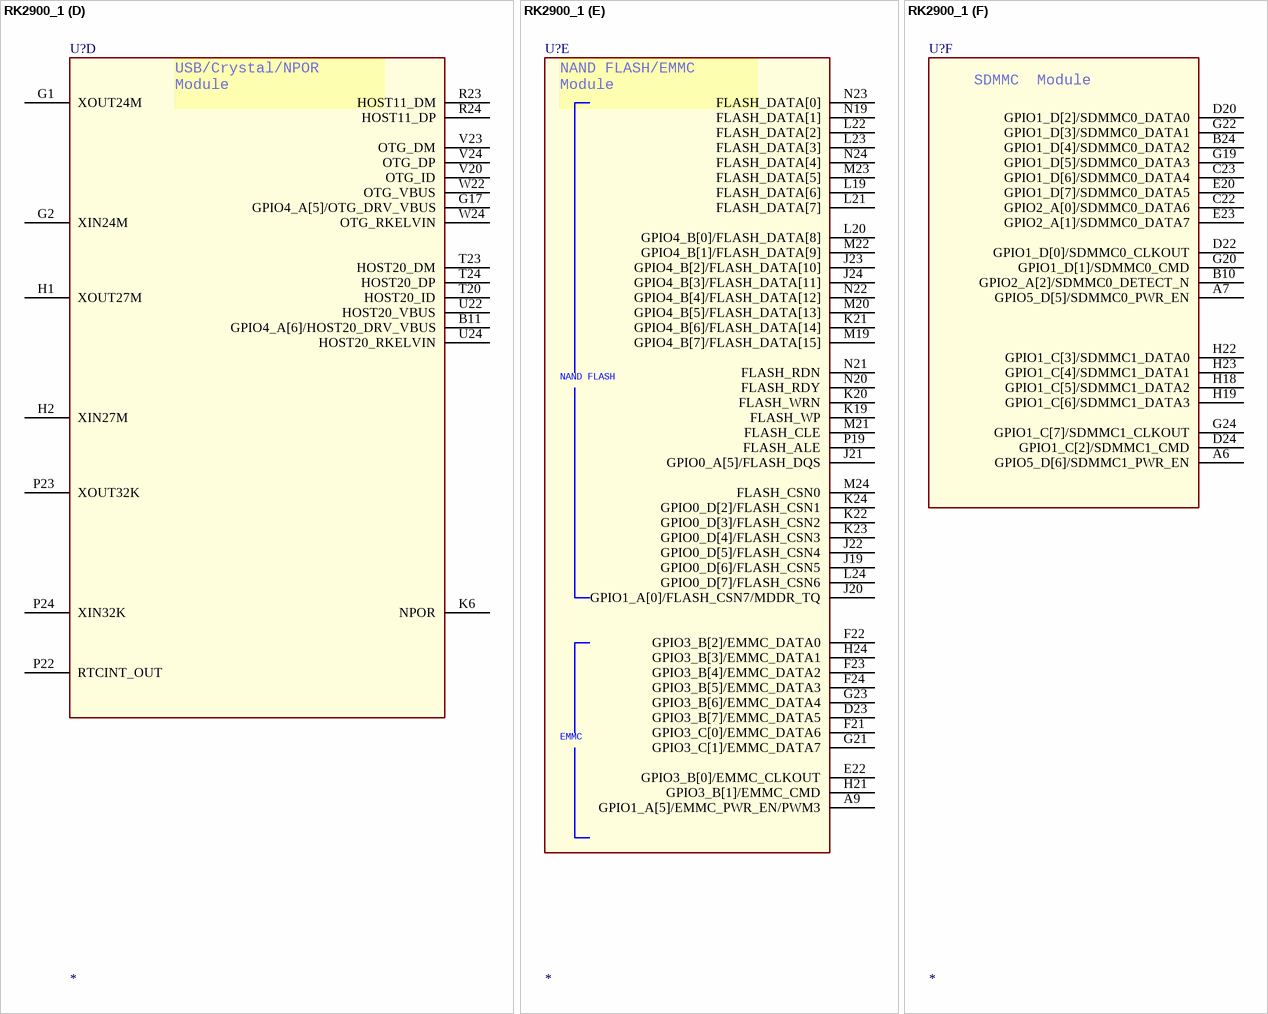
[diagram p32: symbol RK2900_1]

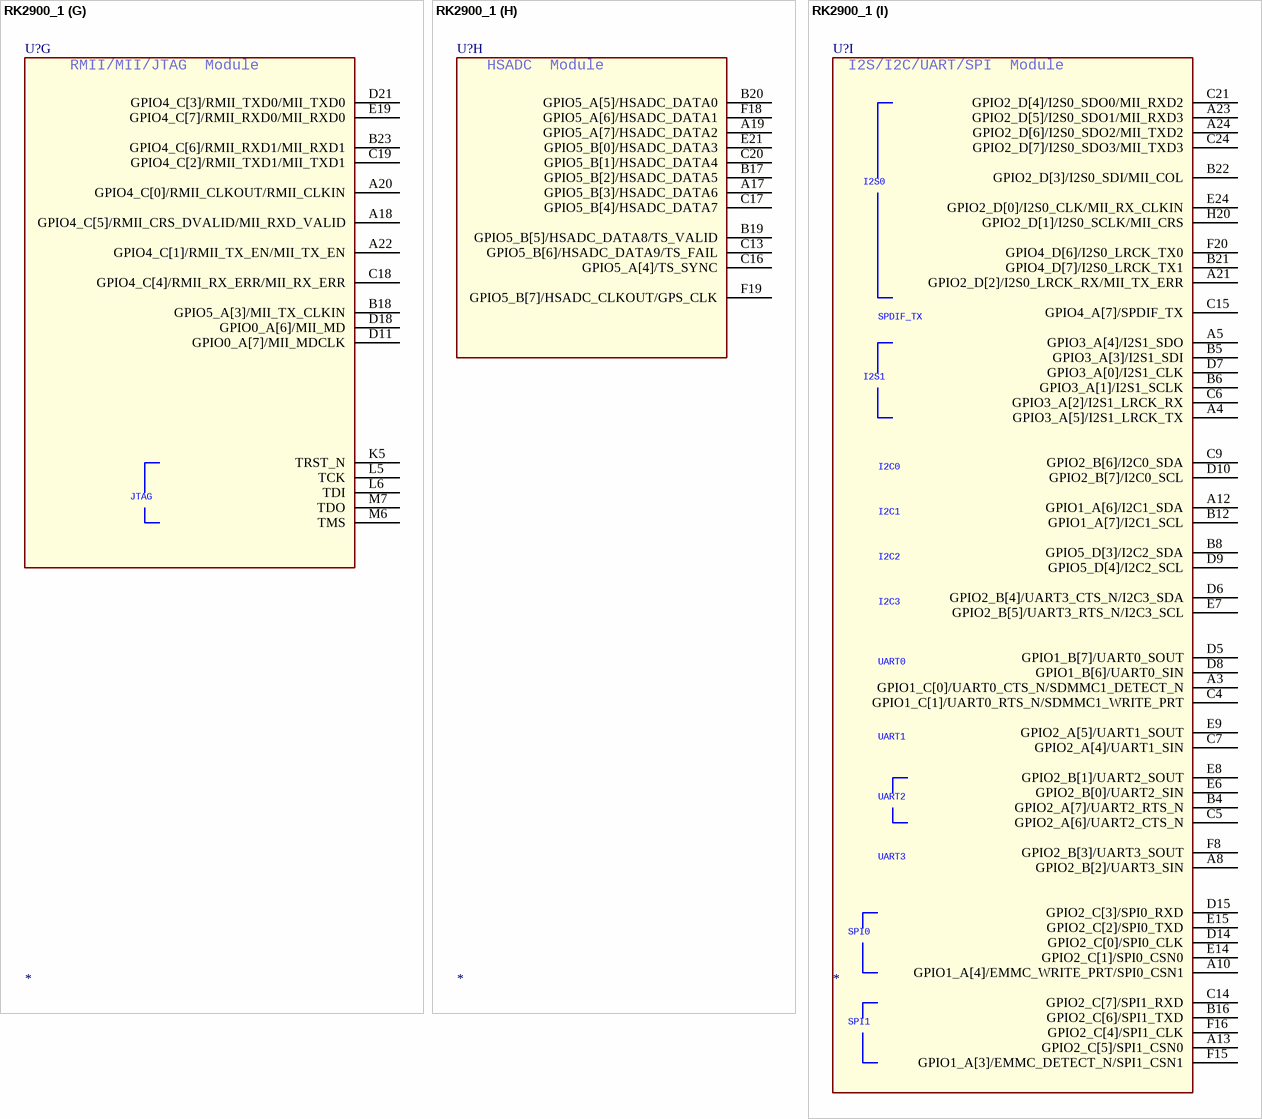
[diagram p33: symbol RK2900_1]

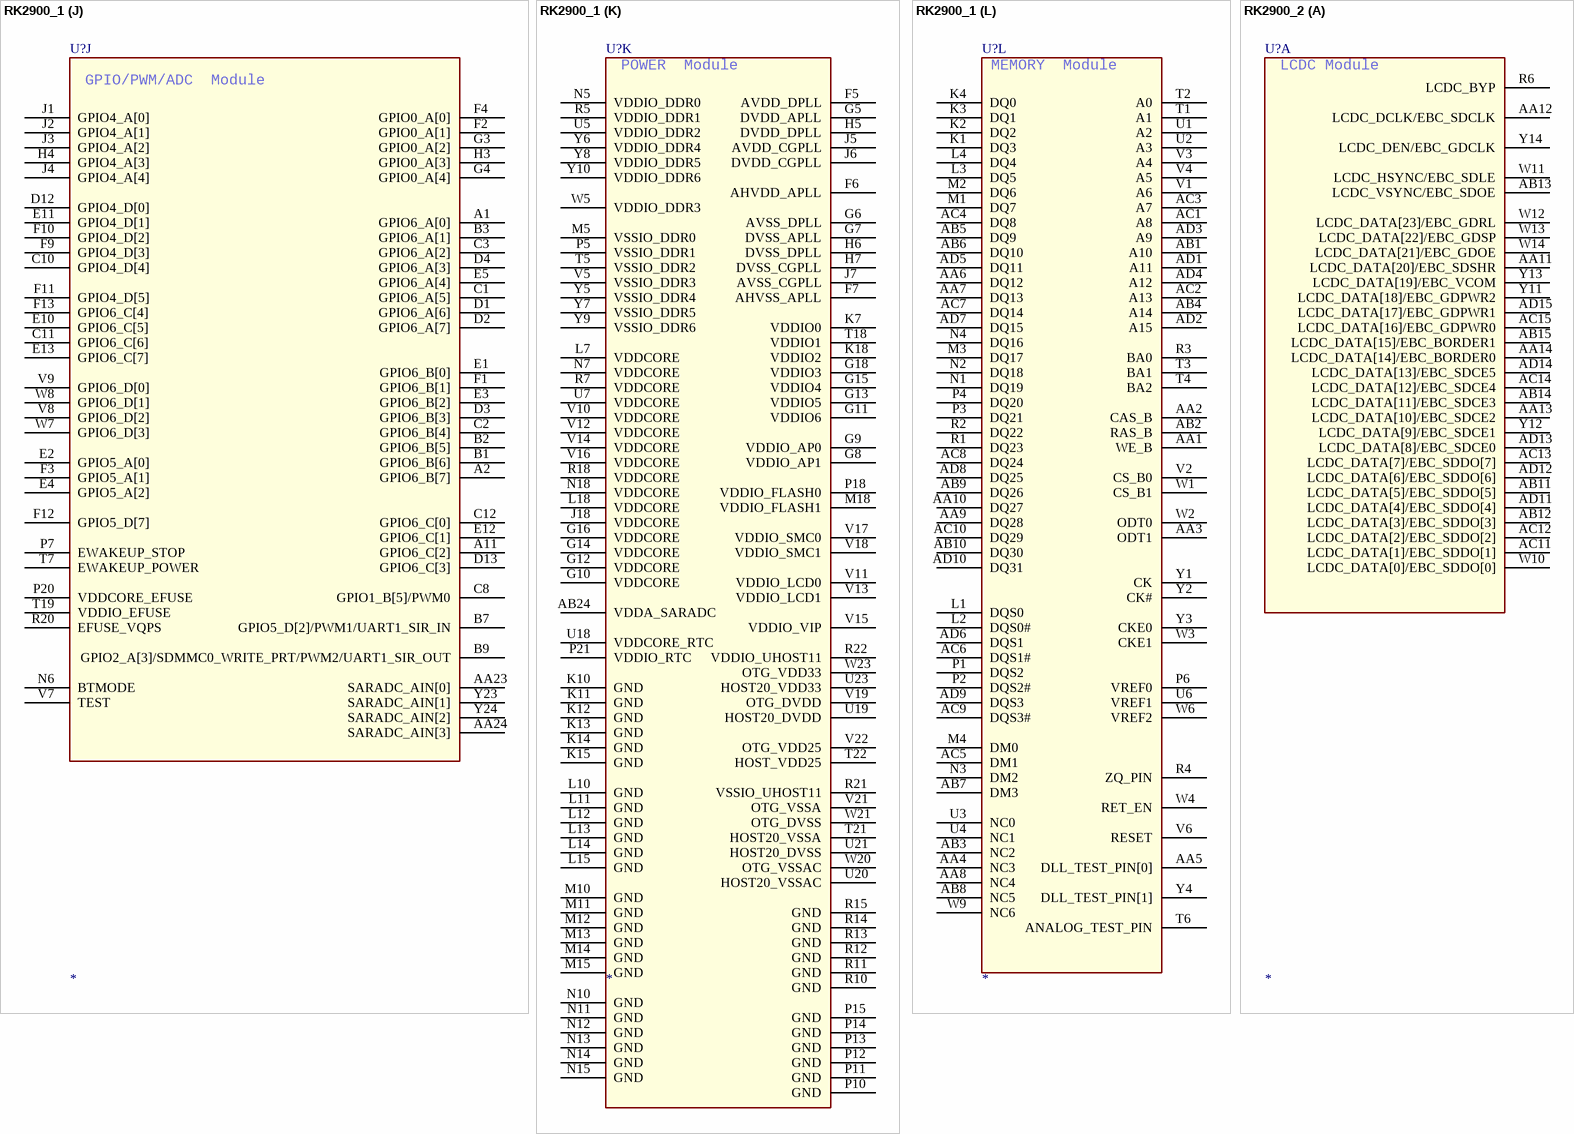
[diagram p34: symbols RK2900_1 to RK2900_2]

## RK2900_1
designator U?
footprint BGA512
part A pins: AA11 LCDC_DATA[20]/EBC_SDSHR, AA12 LCDC_DCLK/EBC_SDCLK, AA13 LCDC_DATA[10]/EBC_SDCE2, AA14 LCDC_DATA[14]/EBC_BORDER0, AB11 LCDC_DATA[5]/EBC_SDDO[5], AB12 LCDC_DATA[3]/EBC_SDDO[3], AB13 LCDC_VSYNC/EBC_SDOE, AB14 LCDC_DATA[11]/EBC_SDCE3, AB15 LCDC_DATA[15]/EBC_BORDER1, AC11 LCDC_DATA[1]/EBC_SDDO[1], AC12 LCDC_DATA[2]/EBC_SDDO[2], AC13 LCDC_DATA[7]/EBC_SDDO[7], AC14 LCDC_DATA[12]/EBC_SDCE4, AC15 LCDC_DATA[16]/EBC_GDPWR0, AD11 LCDC_DATA[4]/EBC_SDDO[4], AD12 LCDC_DATA[6]/EBC_SDDO[6], AD13 LCDC_DATA[8]/EBC_SDCE0, AD14 LCDC_DATA[13]/EBC_SDCE5, AD15 LCDC_DATA[17]/EBC_GDPWR1, R6 LCDC_BYP, W10 LCDC_DATA[0]/EBC_SDDO[0], W11 LCDC_HSYNC/EBC_SDLE, W12 LCDC_DATA[23]/EBC_GDRL, W13 LCDC_DATA[22]/EBC_GDSP, W14 LCDC_DATA[21]/EBC_GDOE, Y11 LCDC_DATA[18]/EBC_GDPWR2, Y12 LCDC_DATA[9]/EBC_SDCE1, Y13 LCDC_DATA[19]/EBC_VCOM, Y14 LCDC_DEN/EBC_GDCLK
part B pins: AA15 VIP_DATAIN[10], AA16 GPIO1_B[0]/VIP_DATAIN[0], AA17 GPIO1_B[1]/VIP_DATAIN[1], AB16 VIP_DATAIN[5], AB17 VIP_DATAIN[8], AB18 VIP_VSYNC, AC16 VIP_DATAIN[6], AC17 VIP_HREF, AC18 GPIO1_B[3]/VIP_DATAIN[3], AD16 VIP_DATAIN[9], AD17 VIP_CLKIN, AD18 GPIO1_B[2]/VIP_DATAIN[2], W15 VIP_DATAIN[4], W16 GPIO1_B[4]/VIP_CLKOUT, Y15 VIP_DATAIN[11], Y16 VIP_DATAIN[7]
part C pins: A14 GPIO3_C[2]/SMC_ADDR[13]/HOST_DATA[13], A15 GPIO3_D[1]/SMC_ADDR[19]/HOST_ADDR1, A16 GPIO3_C[4]/SMC_ADDR[11]/HOST_DATA[11], AA18 GPIO5_C[1]/EBC_SDDO[1]/SMC_DATA[1], AA19 GPIO0_B[6]/EBC_SDSHR/SMC_BLSN1/HOST_INT, AA20 GPIO5_C[5]/EBC_SDDO[5]/SMC_DATA[5], AA21 GPIO0_B[1]/EBC_SDCE1/SMC_ADDR[1]/HOST_DATA[1], AA22 GPIO0_C[5]/EBC_SDCE3/SMC_DATA[13], AB19 GPIO0_C[2]/EBC_GDPWR0/SMC_DATA[10], AB20 GPIO5_C[6]/EBC_SDDO[6]/SMC_DATA[6], AB21 GPIO0_D[0]/EBC_SDOE/SMC_ADVN, AB22 GPIO0_B[7]/EBC_GDOE/SMC_OEN, AB23 GPIO0_C[3]/EBC_GDPWR1/SMC_DATA[11], AC19 GPIO5_C[2]/EBC_SDDO[2]/SMC_DATA[2], AC20 GPIO5_C[7]/EBC_SDDO[7]/SMC_DATA[7], AC21 GPIO0_D[1]/EBC_GDCLK/SMC_ADDR[4]/HOST_DATA[4], AC22 GPIO0_B[3]/EBC_BORDER0/SMC_ADDR[3]/HOST_DATA[3], AC23 GPIO0_C[0]/EBC_GDSP/SMC_DATA[8], AC24 GPIO0_C[6]/EBC_SDCE4/SMC_DATA[14], AD19 GPIO5_C[3]/EBC_SDDO[3]/SMC_DATA[3], AD20 GPIO0_B[0]/EBC_SDCE0/SMC_ADDR[0]/HOST_DATA[0], AD21 GPIO0_B[2]/EBC_SDCE2/SMC_ADDR[2]/HOST_DATA[2], AD22 GPIO0_B[4]/EBC_BORDER1/SMC_WEN, AD23 GPIO0_C[1]/EBC_GDRL/SMC_DATA[9], AD24 GPIO0_C[7]/EBC_SDCE5/SMC_DATA[15], B13 GPIO3_A[7]/SMC_ADDR[15]/HOST_DATA[15], B14 GPIO3_C[6]/SMC_ADDR[16]/HOST_DATA[16], B15 GPIO3_C[5]/SMC_ADDR[12]/HOST_DATA[12], D16 GPIO3_C[7]/SMC_ADDR[17]/HOST_DATA[17], D17 GPIO3_D[2]/HOST_CSN, D19 GPIO3_D[4]/HOST_WRN, E16 GPIO3_C[3]/SMC_ADDR[10]/HOST_DATA[10], E17 GPIO3_D[7]/SMC_ADDR[9]/HOST_DATA[9], E18 GPIO3_D[3]/HOST_RDN, F14 GPIO3_D[0]/SMC_ADDR[18]/HOST_ADDR0, F17 GPIO3_A[6]/SMC_ADDR[14]/HOST_DATA[14], R19 GPIO3_D[6]/SMC_ADDR[8]/HOST_DATA[8], W17 GPIO1_A[1]/SMC_CSN0, W18 GPIO5_C[4]/EBC_SDDO[4]/SMC_DATA[4], W19 GPIO5_D[1]/EBC_SDCLK/SMC_ADDR[6]/HOST_DATA[6], Y17 GPIO0_B[5]/EBC_VCOM/SMC_BLSN0, Y18 GPIO5_C[0]/EBC_SDDO[0]/SMC_DATA[0], Y19 GPIO5_D[0]/EBC_SDLE/SMC_ADDR[5]/HOST_DATA[5], Y20 GPIO0_C[4]/EBC_GDPWR2/SMC_DATA[12], Y21 GPIO1_A[2]/SMC_CSN1, Y22 GPIO3_D[5]/SMC_ADDR[7]/HOST_DATA[7]
part D pins: B11 GPIO4_A[6]/HOST20_DRV_VBUS, G1 XOUT24M, G2 XIN24M, G17 GPIO4_A[5]/OTG_DRV_VBUS, H1 XOUT27M, H2 XIN27M, K6 NPOR, P22 RTCINT_OUT, P23 XOUT32K, P24 XIN32K, R23 HOST11_DM, R24 HOST11_DP, T20 HOST20_ID, T23 HOST20_DM, T24 HOST20_DP, U22 HOST20_VBUS, U24 HOST20_RKELVIN, V20 OTG_ID, V23 OTG_DM, V24 OTG_DP, W22 OTG_VBUS, W24 OTG_RKELVIN
part E pins: A9 GPIO1_A[5]/EMMC_PWR_EN/PWM3, D23 GPIO3_B[7]/EMMC_DATA5, E22 GPIO3_B[0]/EMMC_CLKOUT, F21 GPIO3_C[0]/EMMC_DATA6, F22 GPIO3_B[2]/EMMC_DATA0, F23 GPIO3_B[4]/EMMC_DATA2, F24 GPIO3_B[5]/EMMC_DATA3, G21 GPIO3_C[1]/EMMC_DATA7, G23 GPIO3_B[6]/EMMC_DATA4, H21 GPIO3_B[1]/EMMC_CMD, H24 GPIO3_B[3]/EMMC_DATA1, J19 GPIO0_D[6]/FLASH_CSN5, J20 GPIO1_A[0]/FLASH_CSN7/MDDR_TQ, J21 GPIO0_A[5]/FLASH_DQS, J22 GPIO0_D[5]/FLASH_CSN4, J23 GPIO4_B[2]/FLASH_DATA[10], J24 GPIO4_B[3]/FLASH_DATA[11], K19 FLASH_WP, K20 FLASH_WRN, K21 GPIO4_B[6]/FLASH_DATA[14], K22 GPIO0_D[3]/FLASH_CSN2, K23 GPIO0_D[4]/FLASH_CSN3, K24 GPIO0_D[2]/FLASH_CSN1, L19 FLASH_DATA[6], L20 GPIO4_B[0]/FLASH_DATA[8], L21 FLASH_DATA[7], L22 FLASH_DATA[2], L23 FLASH_DATA[3], L24 GPIO0_D[7]/FLASH_CSN6, M19 GPIO4_B[7]/FLASH_DATA[15], M20 GPIO4_B[5]/FLASH_DATA[13], M21 FLASH_CLE, M22 GPIO4_B[1]/FLASH_DATA[9], M23 FLASH_DATA[5], M24 FLASH_CSN0, N19 FLASH_DATA[1], N20 FLASH_RDY, N21 FLASH_RDN, N22 GPIO4_B[4]/FLASH_DATA[12], N23 FLASH_DATA[0], N24 FLASH_DATA[4], P19 FLASH_ALE
part F pins: A6 GPIO5_D[6]/SDMMC1_PWR_EN, A7 GPIO5_D[5]/SDMMC0_PWR_EN, B10 GPIO2_A[2]/SDMMC0_DETECT_N, B24 GPIO1_D[4]/SDMMC0_DATA2, C22 GPIO2_A[0]/SDMMC0_DATA6, C23 GPIO1_D[6]/SDMMC0_DATA4, D20 GPIO1_D[2]/SDMMC0_DATA0, D22 GPIO1_D[0]/SDMMC0_CLKOUT, D24 GPIO1_C[2]/SDMMC1_CMD, E20 GPIO1_D[7]/SDMMC0_DATA5, E23 GPIO2_A[1]/SDMMC0_DATA7, G19 GPIO1_D[5]/SDMMC0_DATA3, G20 GPIO1_D[1]/SDMMC0_CMD, G22 GPIO1_D[3]/SDMMC0_DATA1, G24 GPIO1_C[7]/SDMMC1_CLKOUT, H18 GPIO1_C[5]/SDMMC1_DATA2, H19 GPIO1_C[6]/SDMMC1_DATA3, H22 GPIO1_C[3]/SDMMC1_DATA0, H23 GPIO1_C[4]/SDMMC1_DATA1
part G pins: A18 GPIO4_C[5]/RMII_CRS_DVALID/MII_RXD_VALID, A20 GPIO4_C[0]/RMII_CLKOUT/RMII_CLKIN, A22 GPIO4_C[1]/RMII_TX_EN/MII_TX_EN, B18 GPIO5_A[3]/MII_TX_CLKIN, B23 GPIO4_C[6]/RMII_RXD1/MII_RXD1, C18 GPIO4_C[4]/RMII_RX_ERR/MII_RX_ERR, C19 GPIO4_C[2]/RMII_TXD1/MII_TXD1, D11 GPIO0_A[7]/MII_MDCLK, D18 GPIO0_A[6]/MII_MD, D21 GPIO4_C[3]/RMII_TXD0/MII_TXD0, E19 GPIO4_C[7]/RMII_RXD0/MII_RXD0, K5 TRST_N, L5 TCK, L6 TDI, M6 TMS, M7 TDO
part H pins: A17 GPIO5_B[3]/HSADC_DATA6, A19 GPIO5_A[7]/HSADC_DATA2, B17 GPIO5_B[2]/HSADC_DATA5, B19 GPIO5_B[5]/HSADC_DATA8/TS_VALID, B20 GPIO5_A[5]/HSADC_DATA0, C13 GPIO5_B[6]/HSADC_DATA9/TS_FAIL, C16 GPIO5_A[4]/TS_SYNC, C17 GPIO5_B[4]/HSADC_DATA7, C20 GPIO5_B[1]/HSADC_DATA4, E21 GPIO5_B[0]/HSADC_DATA3, F18 GPIO5_A[6]/HSADC_DATA1, F19 GPIO5_B[7]/HSADC_CLKOUT/GPS_CLK
part I pins: A3 GPIO1_C[0]/UART0_CTS_N/SDMMC1_DETECT_N, A4 GPIO3_A[5]/I2S1_LRCK_TX, A5 GPIO3_A[4]/I2S1_SDO, A8 GPIO2_B[2]/UART3_SIN, A10 GPIO1_A[4]/EMMC_WRITE_PRT/SPI0_CSN1, A12 GPIO1_A[6]/I2C1_SDA, A13 GPIO2_C[5]/SPI1_CSN0, A21 GPIO2_D[2]/I2S0_LRCK_RX/MII_TX_ERR, A23 GPIO2_D[5]/I2S0_SDO1/MII_RXD3, A24 GPIO2_D[6]/I2S0_SDO2/MII_TXD2, B4 GPIO2_A[7]/UART2_RTS_N, B5 GPIO3_A[3]/I2S1_SDI, B6 GPIO3_A[1]/I2S1_SCLK, B8 GPIO5_D[3]/I2C2_SDA, B12 GPIO1_A[7]/I2C1_SCL, B16 GPIO2_C[6]/SPI1_TXD, B21 GPIO4_D[7]/I2S0_LRCK_TX1, B22 GPIO2_D[3]/I2S0_SDI/MII_COL, C4 GPIO1_C[1]/UART0_RTS_N/SDMMC1_WRITE_PRT, C5 GPIO2_A[6]/UART2_CTS_N, C6 GPIO3_A[2]/I2S1_LRCK_RX, C7 GPIO2_A[4]/UART1_SIN, C9 GPIO2_B[6]/I2C0_SDA, C14 GPIO2_C[7]/SPI1_RXD, C15 GPIO4_A[7]/SPDIF_TX, C21 GPIO2_D[4]/I2S0_SDO0/MII_RXD2, C24 GPIO2_D[7]/I2S0_SDO3/MII_TXD3, D5 GPIO1_B[7]/UART0_SOUT, D6 GPIO2_B[4]/UART3_CTS_N/I2C3_SDA, D7 GPIO3_A[0]/I2S1_CLK, D8 GPIO1_B[6]/UART0_SIN, D9 GPIO5_D[4]/I2C2_SCL, D10 GPIO2_B[7]/I2C0_SCL, D14 GPIO2_C[0]/SPI0_CLK, D15 GPIO2_C[3]/SPI0_RXD, E6 GPIO2_B[0]/UART2_SIN, E7 GPIO2_B[5]/UART3_RTS_N/I2C3_SCL, E8 GPIO2_B[1]/UART2_SOUT, E9 GPIO2_A[5]/UART1_SOUT, E14 GPIO2_C[1]/SPI0_CSN0, E15 GPIO2_C[2]/SPI0_TXD, E24 GPIO2_D[0]/I2S0_CLK/MII_RX_CLKIN, F8 GPIO2_B[3]/UART3_SOUT, F15 GPIO1_A[3]/EMMC_DETECT_N/SPI1_CSN1, F16 GPIO2_C[4]/SPI1_CLK, F20 GPIO4_D[6]/I2S0_LRCK_TX0, H20 GPIO2_D[1]/I2S0_SCLK/MII_CRS
part J pins: A1 GPIO6_A[0], A2 GPIO6_B[7], A11 GPIO6_C[2], AA23 SARADC_AIN[0], AA24 SARADC_AIN[3], B1 GPIO6_B[6], B2 GPIO6_B[5], B3 GPIO6_A[1], B7 GPIO5_D[2]/PWM1/UART1_SIR_IN, B9 GPIO2_A[3]/SDMMC0_WRITE_PRT/PWM2/UART1_SIR_OUT, C1 GPIO6_A[5], C2 GPIO6_B[4], C3 GPIO6_A[2], C8 GPIO1_B[5]/PWM0, C10 GPIO4_D[4], C11 GPIO6_C[6], C12 GPIO6_C[0], D1 GPIO6_A[6], D2 GPIO6_A[7], D3 GPIO6_B[3], D4 GPIO6_A[3], D12 GPIO4_D[0], D13 GPIO6_C[3], E1 GPIO6_B[0], E2 GPIO5_A[0], E3 GPIO6_B[2], E4 GPIO5_A[2], E5 GPIO6_A[4], E10 GPIO6_C[5], E11 GPIO4_D[1], E12 GPIO6_C[1], E13 GPIO6_C[7], F1 GPIO6_B[1], F2 GPIO0_A[1], F3 GPIO5_A[1], F4 GPIO0_A[0], F9 GPIO4_D[3], F10 GPIO4_D[2], F11 GPIO4_D[5], F12 GPIO5_D[7], F13 GPIO6_C[4], G3 GPIO0_A[2], G4 GPIO0_A[4], H3 GPIO0_A[3], H4 GPIO4_A[3], J1 GPIO4_A[0], J2 GPIO4_A[1], J3 GPIO4_A[2], J4 GPIO4_A[4], N6 BTMODE, P7 EWAKEUP_STOP, P20 VDDCORE_EFUSE, R20 EFUSE_VQPS, T7 EWAKEUP_POWER, T19 VDDIO_EFUSE, V7 TEST, V8 GPIO6_D[2], V9 GPIO6_D[0], W7 GPIO6_D[3], W8 GPIO6_D[1], Y23 SARADC_AIN[1], Y24 SARADC_AIN[2]
part K pins: AB24 VDDA_SARADC, F5 AVDD_DPLL, F6 AHVDD_APLL, F7 AHVSS_APLL, G5 DVDD_APLL, G6 AVSS_DPLL, G7 DVSS_APLL, G8 VDDIO_AP1, G9 VDDIO_AP0, G10 VDDCORE, G11 VDDIO6, G12 VDDCORE, G13 VDDIO5, G14 VDDCORE, G15 VDDIO4, G16 VDDCORE, G18 VDDIO3, H5 DVDD_DPLL, H6 DVSS_DPLL, H7 DVSS_CGPLL, J5 AVDD_CGPLL, J6 DVDD_CGPLL, J7 AVSS_CGPLL, J18 VDDCORE, K7 VDDIO0, K10 GND, K11 GND, K12 GND, K13 GND, K14 GND, K15 GND, K18 VDDIO2, L7 VDDCORE, L10 GND, L11 GND, L12 GND, L13 GND, L14 GND, L15 GND, L18 VDDCORE, M5 VSSIO_DDR0, M10 GND, M11 GND, M12 GND, M13 GND, M14 GND, M15 GND, M18 VDDIO_FLASH1, N5 VDDIO_DDR0, N7 VDDCORE, N10 GND, N11 GND, N12 GND, N13 GND, N14 GND, N15 GND, N18 VDDCORE, P5 VSSIO_DDR1, P10 GND, P11 GND, P12 GND, P13 GND, P14 GND, P15 GND, P18 VDDIO_FLASH0, P21 VDDIO_RTC, R5 VDDIO_DDR1, R7 VDDCORE, R10 GND, R11 GND, R12 GND, R13 GND, R14 GND, R15 GND, R18 VDDCORE, R21 VSSIO_UHOST11, R22 VDDIO_UHOST11, T5 VSSIO_DDR2, T18 VDDIO1, T21 HOST20_VSSA, T22 HOST_VDD25, U5 VDDIO_DDR2, U7 VDDCORE, U18 VDDCORE_RTC, U19 HOST20_DVDD, U20 HOST20_VSSAC, U21 HOST20_DVSS, U23 HOST20_VDD33, V5 VSSIO_DDR3, V10 VDDCORE, V11 VDDIO_LCD0, V12 VDDCORE, V13 VDDIO_LCD1, V14 VDDCORE, V15 VDDIO_VIP, V16 VDDCORE, V17 VDDIO_SMC0, V18 VDDIO_SMC1, V19 OTG_DVDD, V21 OTG_VSSA, V22 OTG_VDD25, W5 VDDIO_DDR3, W20 OTG_VSSAC, W21 OTG_DVSS, W23 OTG_VDD33, Y5 VSSIO_DDR4, Y6 VDDIO_DDR4, Y7 VSSIO_DDR5, Y8 VDDIO_DDR5, Y9 VSSIO_DDR6, Y10 VDDIO_DDR6
part L pins: AA1 WE_B, AA2 CAS_B, AA3 ODT1, AA4 NC3, AA5 DLL_TEST_PIN[0], AA6 DQ12, AA7 DQ13, AA8 NC4, AA9 DQ28, AA10 DQ27, AB1 A10, AB2 RAS_B, AB3 NC2, AB4 A14, AB5 DQ9, AB6 DQ10, AB7 DM3, AB8 NC5, AB9 DQ26, AB10 DQ30, AC1 A8, AC2 A13, AC3 A7, AC4 DQ8, AC5 DM1, AC6 DQS1#, AC7 DQ14, AC8 DQ24, AC9 DQS3#, AC10 DQ29, AD1 A11, AD2 A15, AD3 A9, AD4 A12, AD5 DQ11, AD6 DQS1, AD7 DQ15, AD8 DQ25, AD9 DQS3, AD10 DQ31, K1 DQ3, K2 DQ2, K3 DQ1, K4 DQ0, L1 DQS0, L2 DQS0#, L3 DQ5, L4 DQ4, M1 DQ7, M2 DQ6, M3 DQ17, M4 DM0, N1 DQ19, N2 DQ18, N3 DM2, N4 DQ16, P1 DQS2, P2 DQS2#, P3 DQ21, P4 DQ20, P6 VREF0, R1 DQ23, R2 DQ22, R3 BA0, R4 ZQ_PIN, T1 A1, T2 A0, T3 BA1, T4 BA2, T6 ANALOG_TEST_PIN, U1 A2, U2 A3, U3 NC0, U4 NC1, U6 VREF1, V1 A6, V2 CS_B0, V3 A4, V4 A5, V6 RESET, W1 CS_B1, W2 ODT0, W3 CKE1, W4 RET_EN, W6 VREF2, W9 NC6, Y1 CK, Y2 CK#, Y3 CKE0, Y4 DLL_TEST_PIN[1]

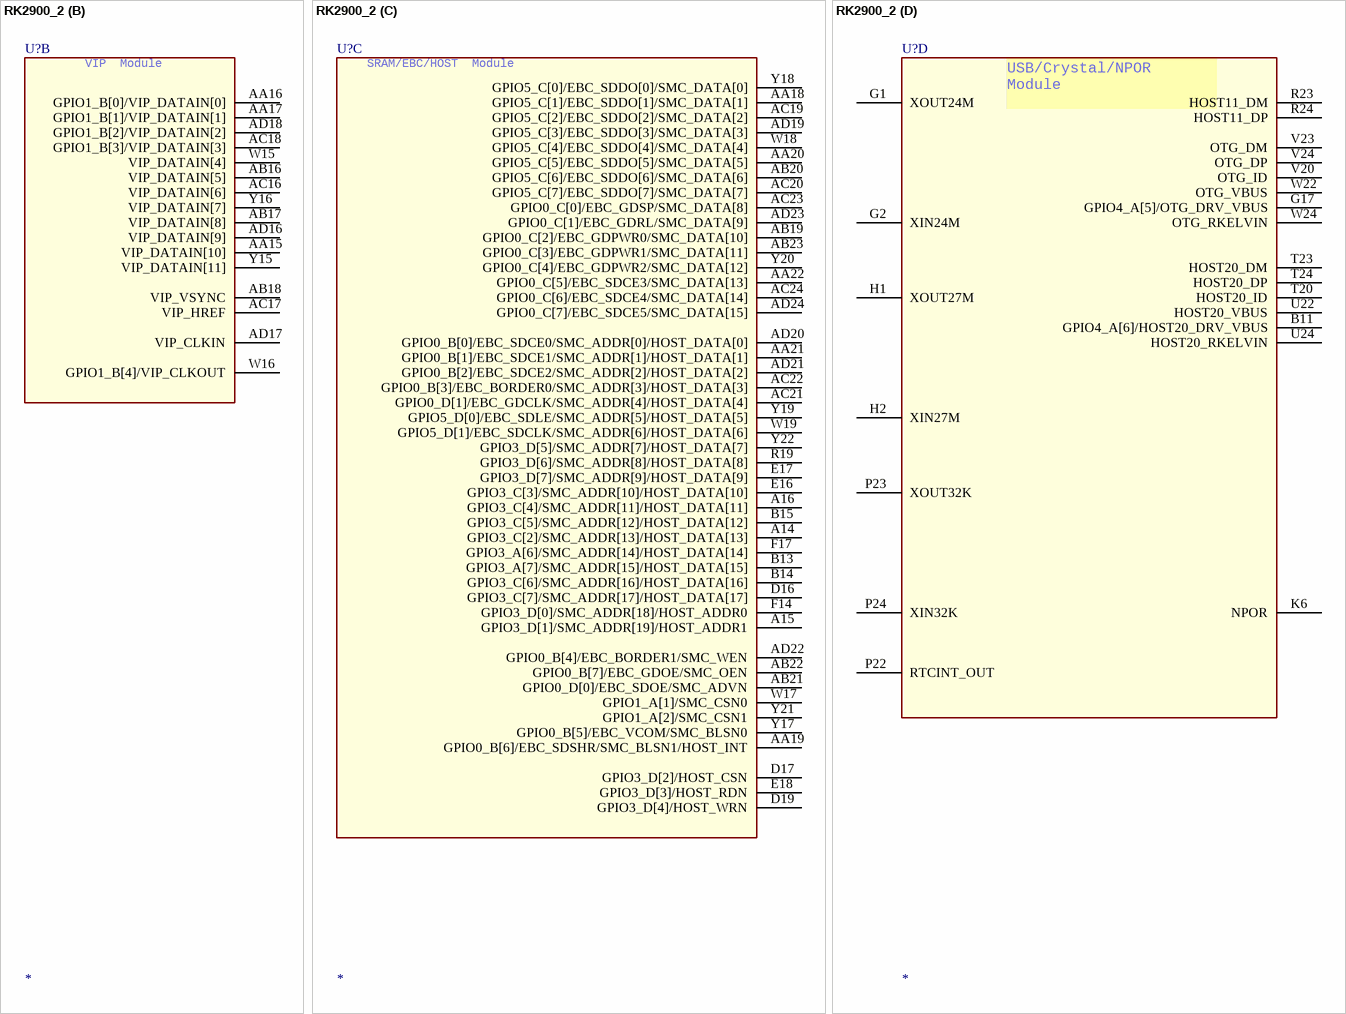
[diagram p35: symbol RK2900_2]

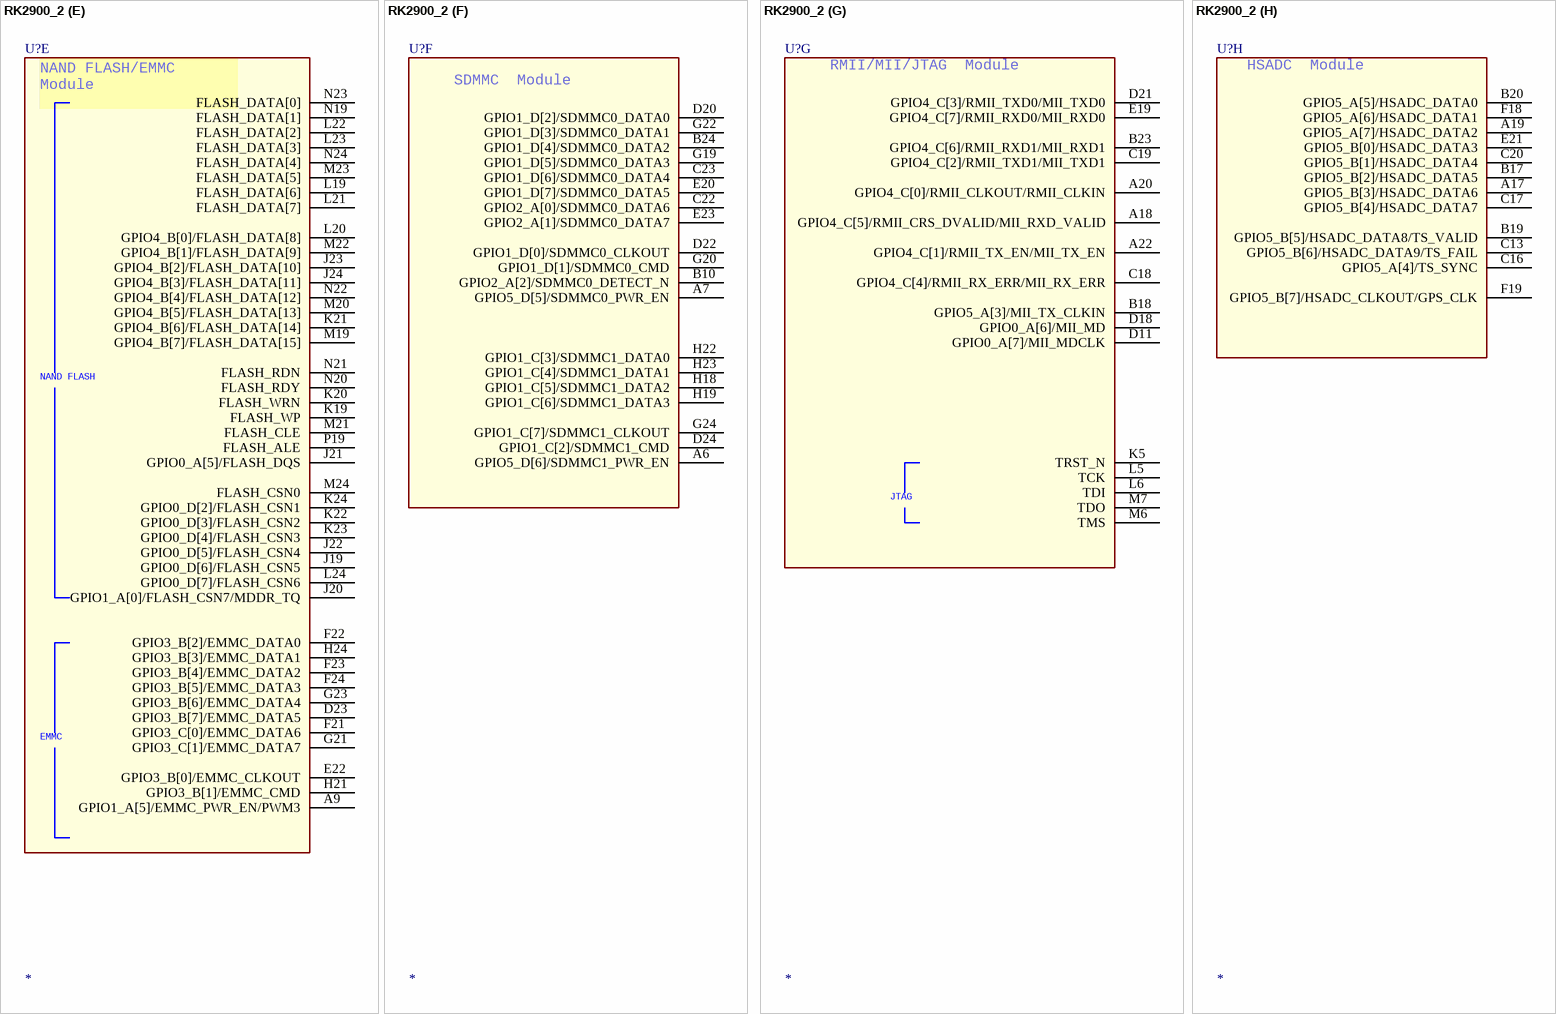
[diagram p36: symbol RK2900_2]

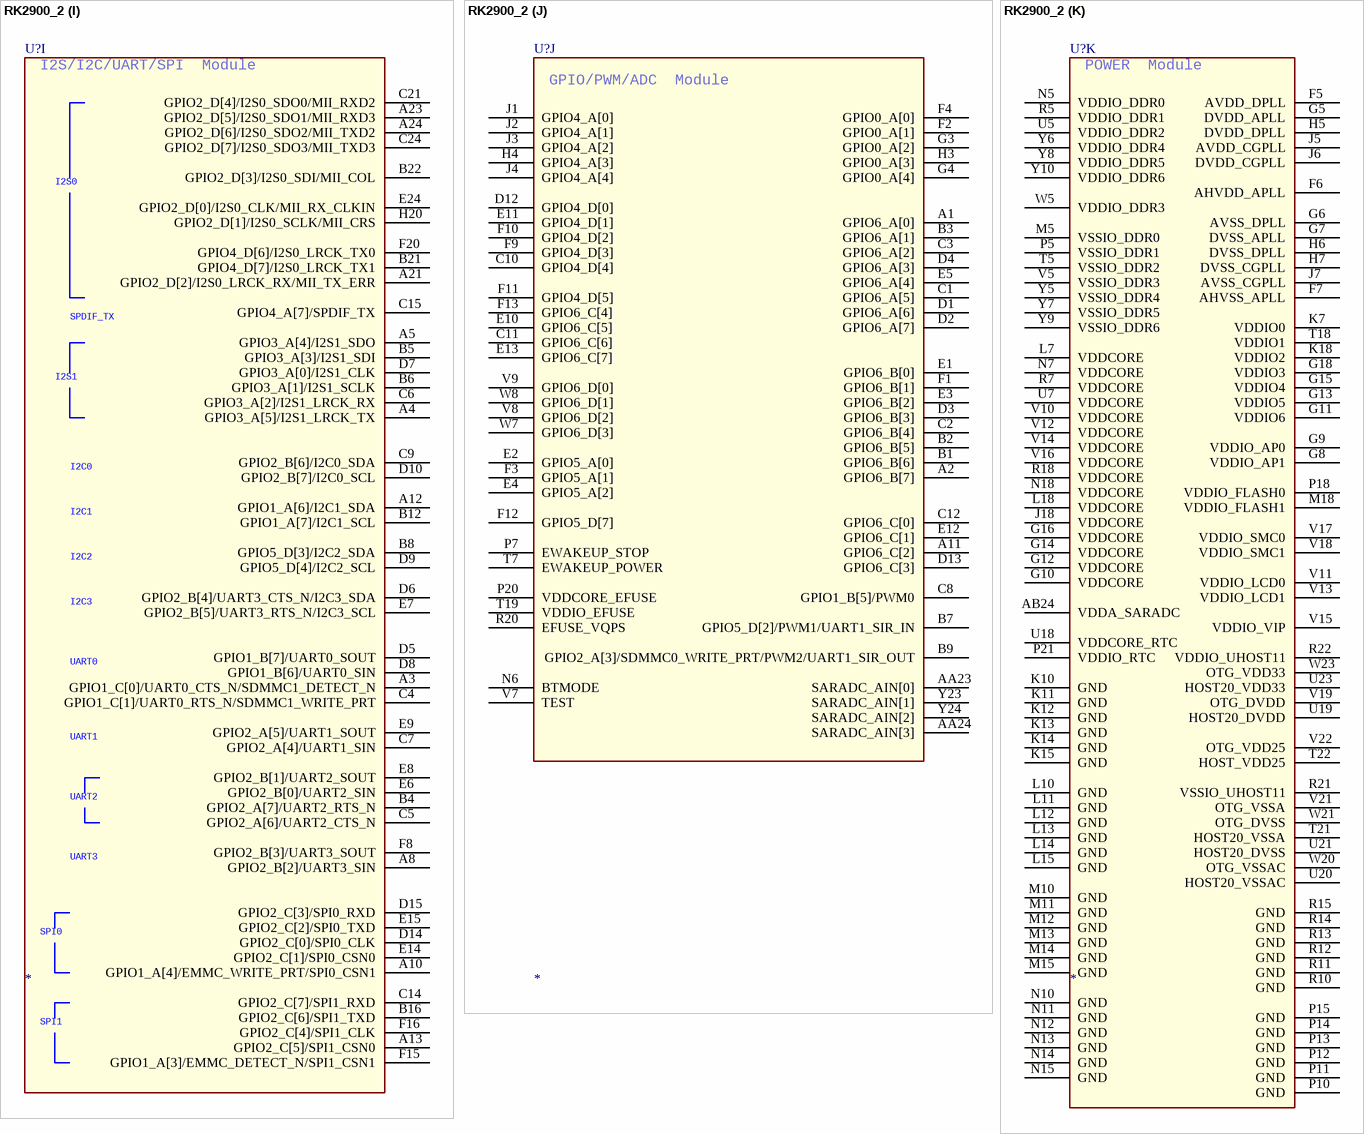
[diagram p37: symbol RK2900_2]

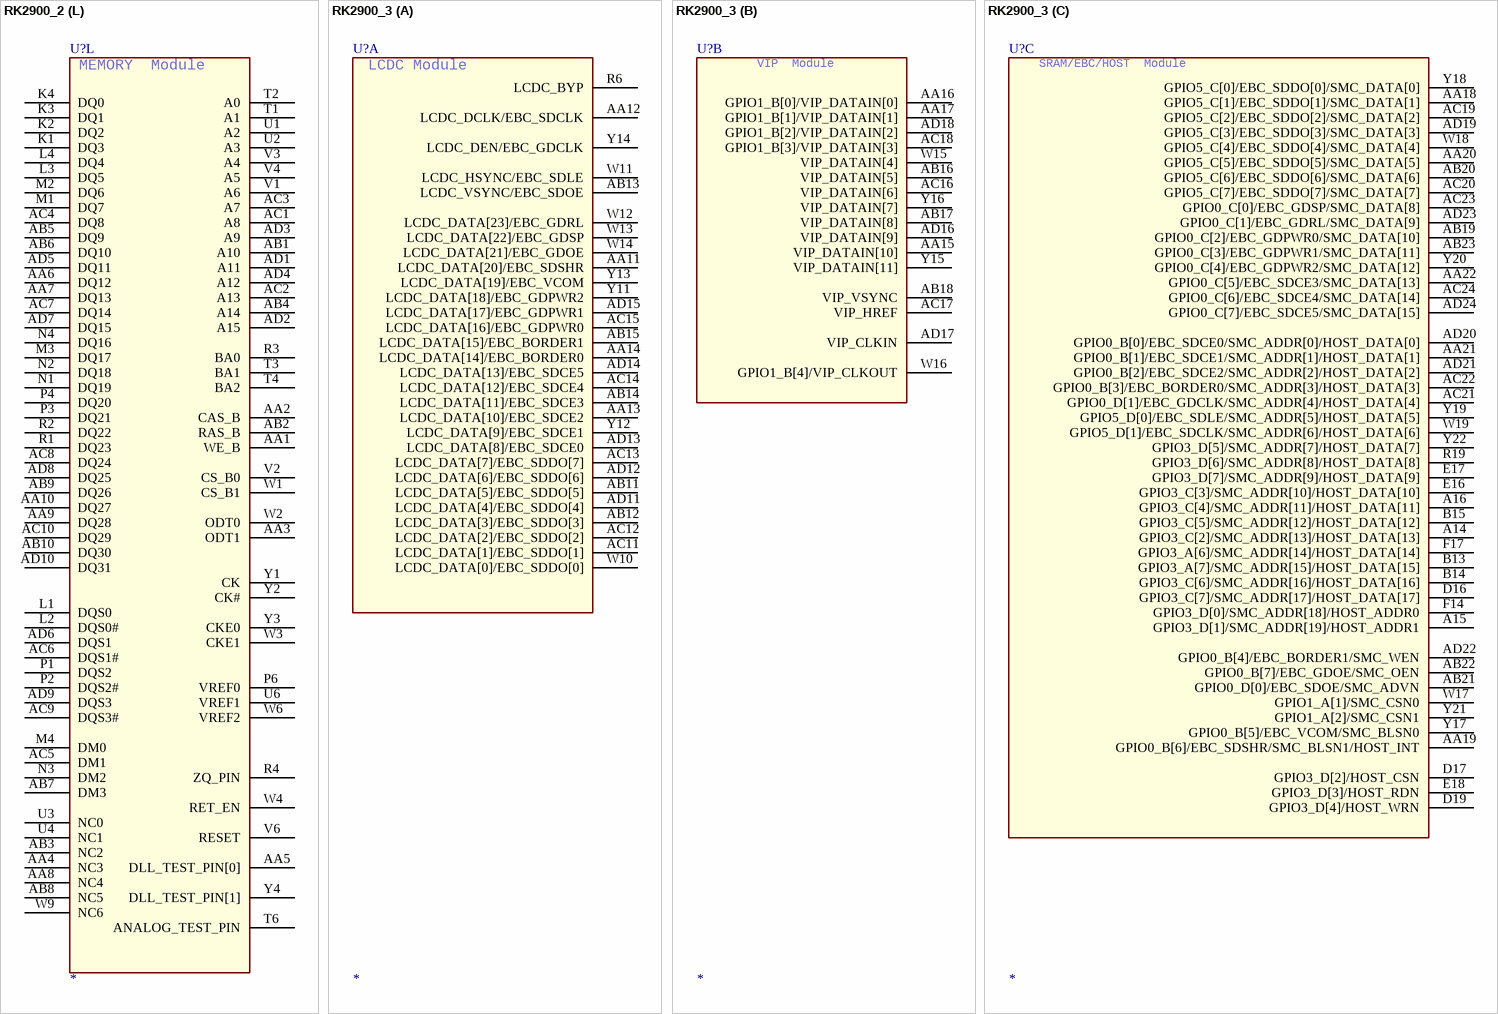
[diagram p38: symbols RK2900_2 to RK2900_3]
